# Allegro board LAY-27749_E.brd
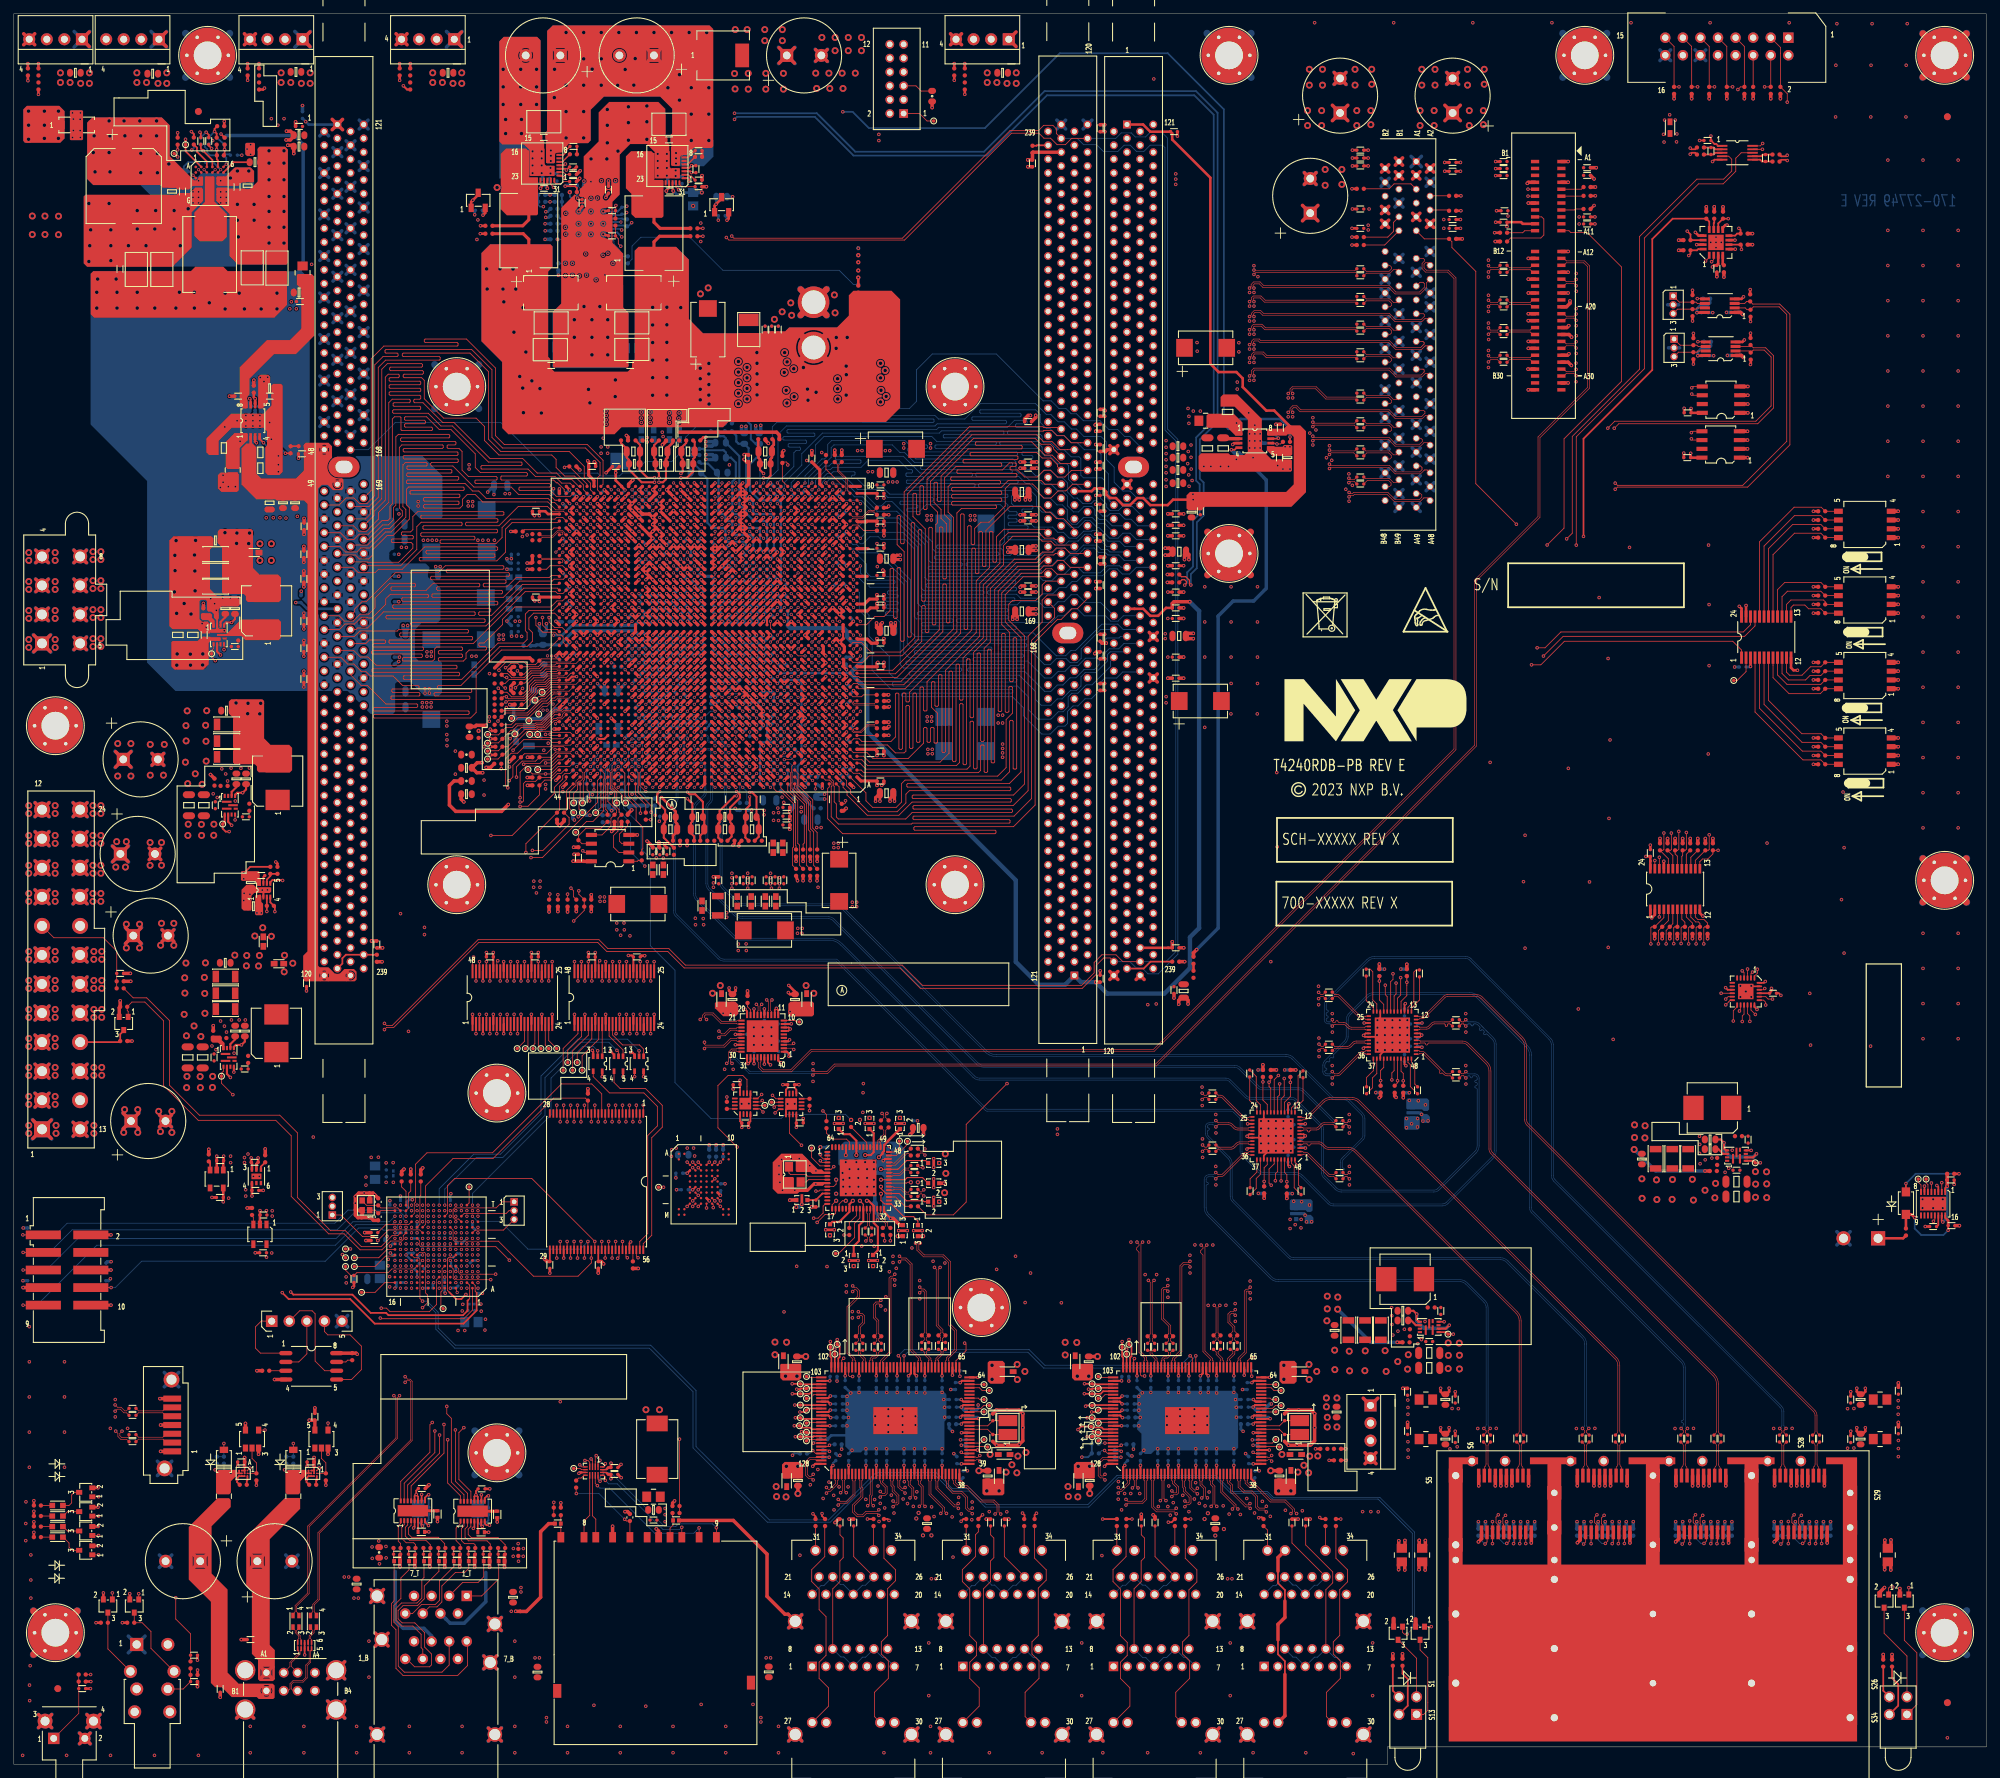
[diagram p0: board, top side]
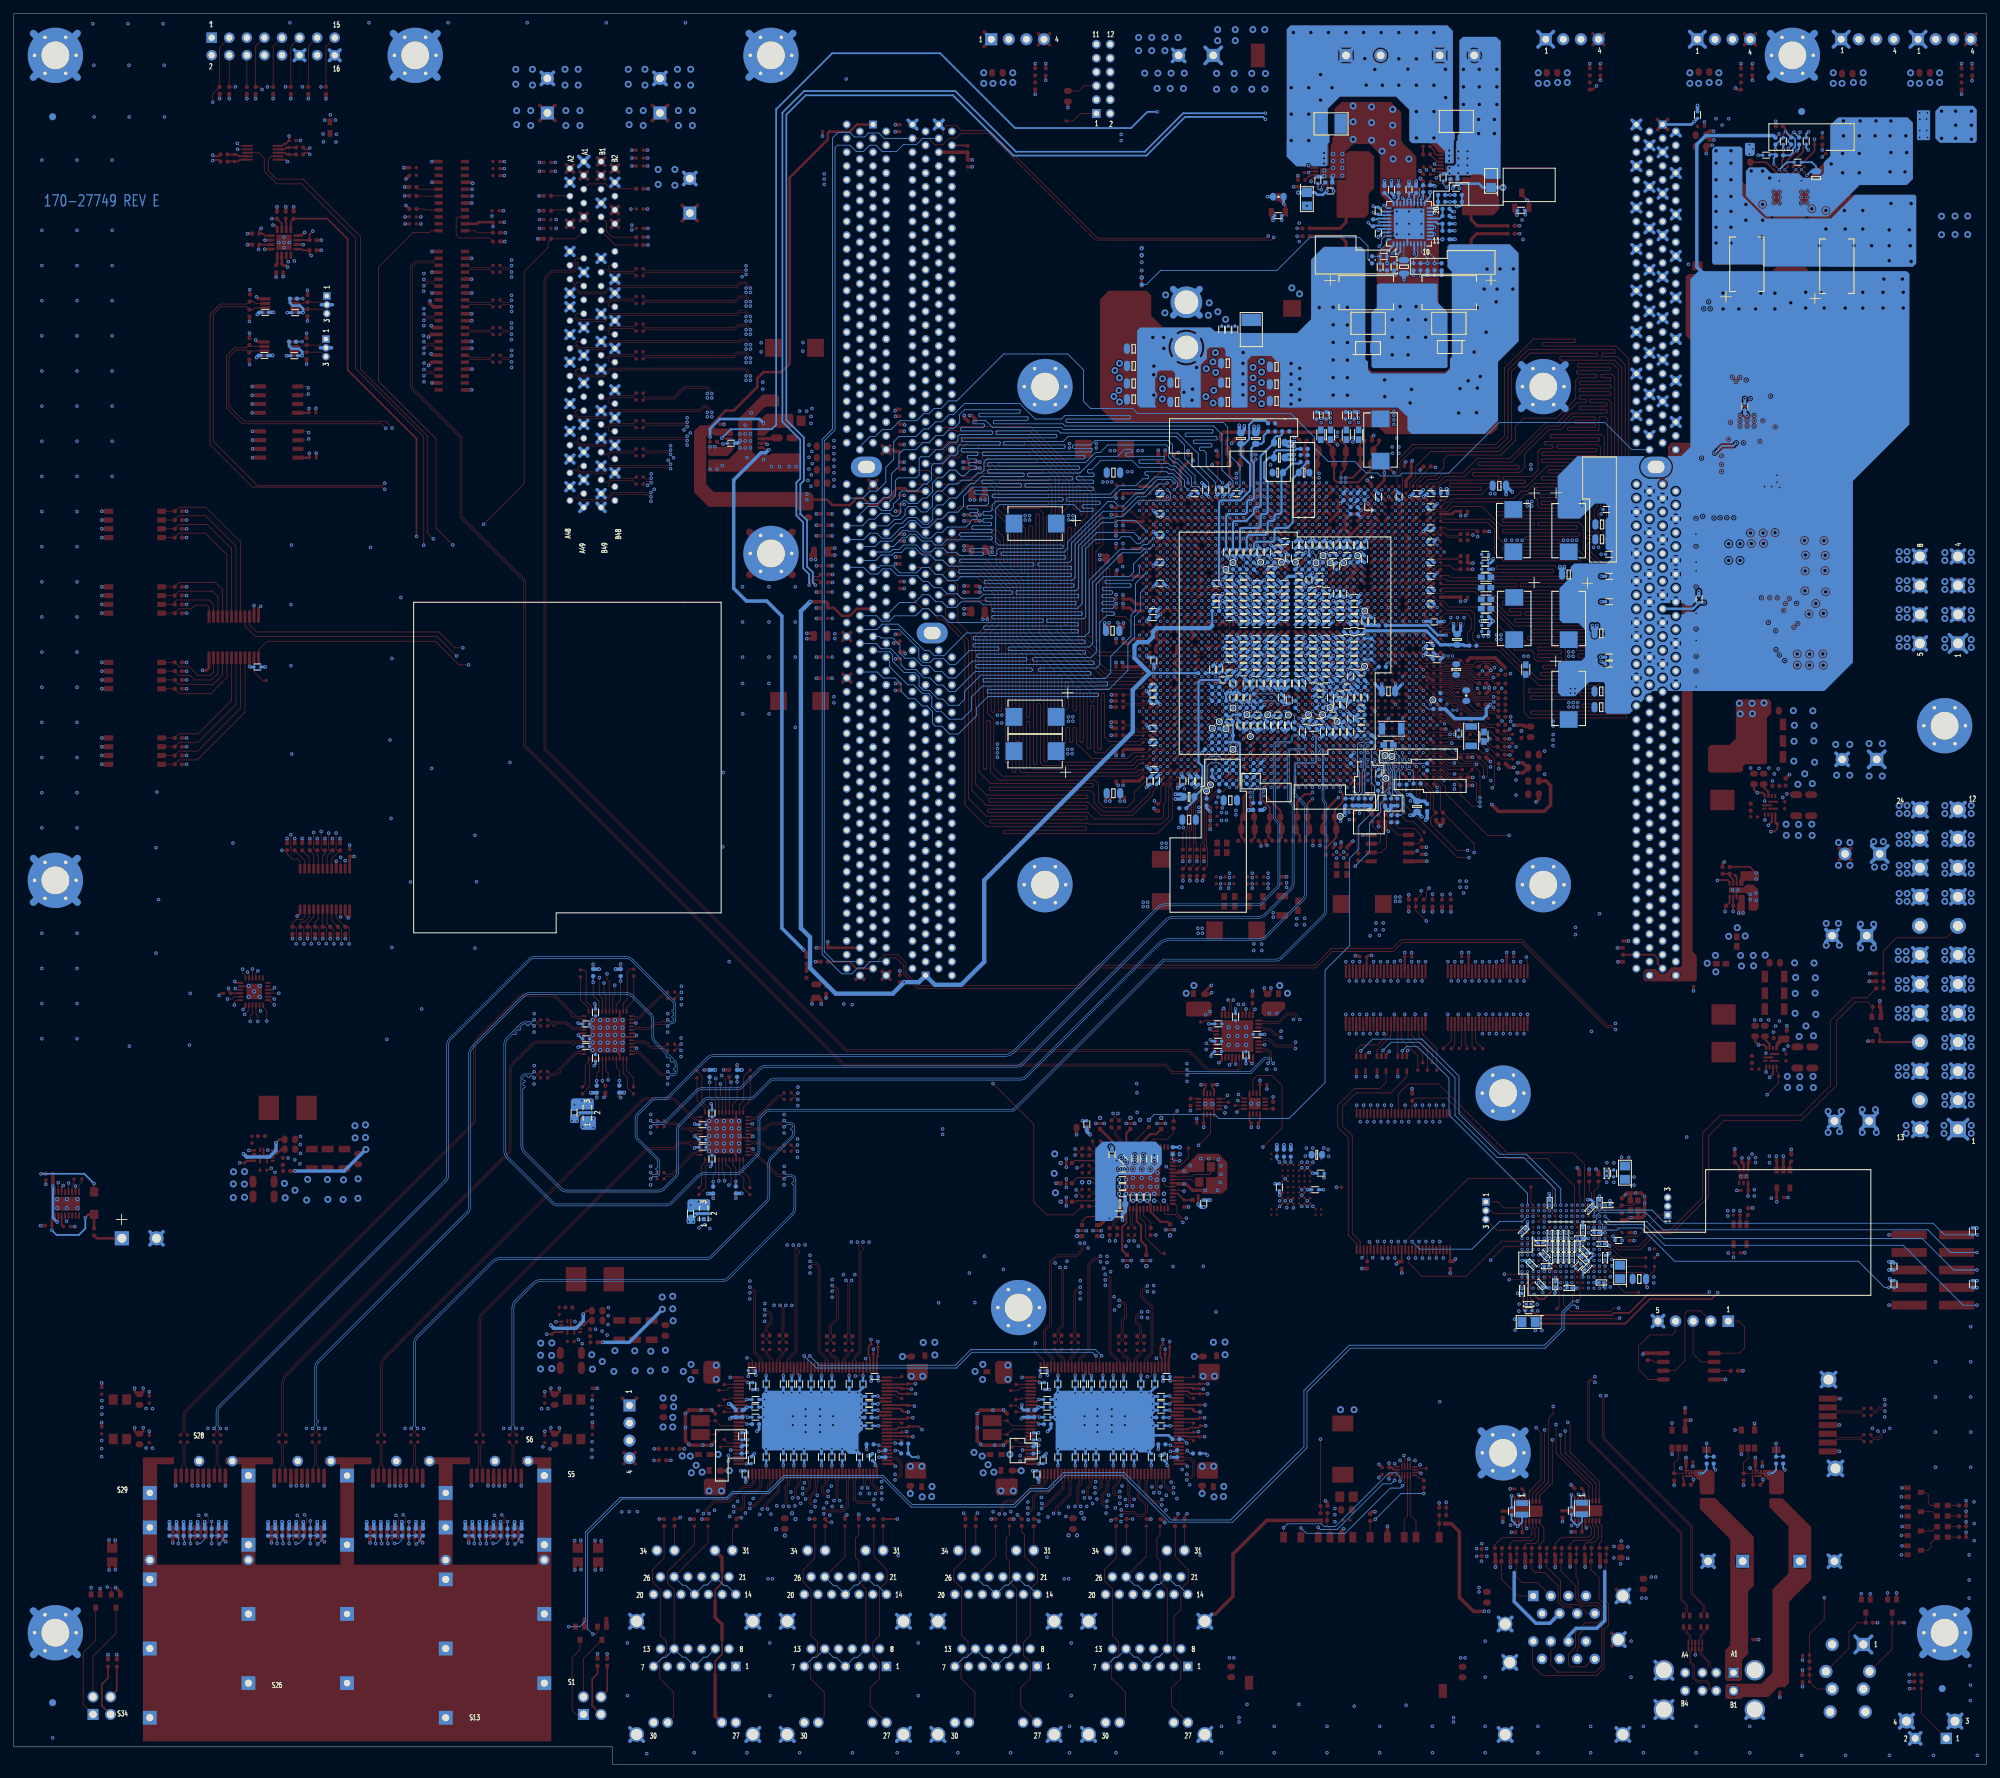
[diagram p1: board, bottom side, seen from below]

Outline 285 x 253 mm; copper layers: TOP, L2_GND_1, L3_INT_1, L4_GND_2, L5_INT_2, L6_GND_3, L7_INT_3, L8_PWR_1, L9_PWR_2, L10_INT_4, L11_GND_4, L12_INT_5, L13_GND_5, L14_INT_6, L15_GND_6, BOTTOM. Coordinates in mm from the lower left corner of the outline.
Outline path: 0,253 285,253 285,2.5 198.5,2.5 198.5,0 0,0 0,253

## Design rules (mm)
constraint set DEFAULT: min track width 0.118
net group ATXPWRGD: nets ATX_PWROK ATXPWRGD
net group CLK_PCIE_REF: nets CLK_PCIE_REF_N CLK_PCIE_REF_P
net group CLKU1: nets CLKU1_N CLKU1_P
net group CLKU2: nets CLKU2_N CLKU2_P
net group CLKU4: nets CLKU4_N CLKU4_P
net group CLKU5: nets CLKU5_N CLKU5_P
net group CLKU6: nets CLKU6_N CLKU6_P
net group CLKU7: nets CLKU7_N CLKU7_P
net group DP1: nets CLK_SE1_100MHZ CLK_SE2_100MHZ
net group DP2: nets EC1_GTX_CLK125 EC2_GTX_CLK125
net group I2C1_SCL: nets I2C1_SCL VDD_SCL
net group I2C1_SDA: nets I2C1_SDA VDD_SDA
net group INJ_DDRCLK: nets DDRCLK INJ_DDRCLK
net group ISOSDHC_CLK: nets ISOSDHC_CLK SDCK
net group LRST_BUTTON_B: nets LRST_BUTTON_B SW_RST_B
net group M1_VREF_ISO: nets M1_VREF_ISO M2_VREF_ISO
net group MC_PCIE_CLK_: nets PCIE_X4_CLK_N PCIE_X4_CLK_P
net group PCIE_REFCLK_: nets PCIE_REFCLK_N PCIE_REFCLK_P
net group RX1_L0_N: nets RX1_L0_N RX1_L0_N_DC
net group RX1_L0_P: nets RX1_L0_P RX1_L0_P_DC
net group RX2_L0_N: nets RX2_L0_N RX2_L0_N_DC
net group RX2_L0_P: nets RX2_L0_P RX2_L0_P_DC
net group RX3_L0_N: nets RX3_L0_N RX3_L0_N_DC
net group RX3_L0_P: nets RX3_L0_P RX3_L0_P_DC
net group RX4_L0_N: nets RX4_L0_N RX4_L0_N_DC
net group RX4_L0_P: nets RX4_L0_P RX4_L0_P_DC
net group SD1_REFCLK1_LVDS_: nets SD1_REFCLK1_N SD1_REFCLK1_P
net group SD2_REFCLK1_LVDS_: nets SD2_REFCLK1_N SD2_REFCLK1_P
net group SD2_REFCLK2_: nets SD2_REFCLK2_N SD2_REFCLK2_P
net group SD2_RX0_N: nets SD2_RX0_N XRX1_DOUTN
net group SD2_RX0_P: nets SD2_RX0_P XRX1_DOUTP
net group SD2_RX1_N: nets SD2_RX1_N XRX2_DOUTN
net group SD2_RX1_P: nets SD2_RX1_P XRX2_DOUTP
net group SD2_RX2_N: nets SD2_RX2_N XRX3_DOUTN
net group SD2_RX2_P: nets SD2_RX2_P XRX3_DOUTP
net group SD2_RX3_N: nets SD2_RX3_N XRX4_DOUTN
net group SD2_RX3_P: nets SD2_RX3_P XRX4_DOUTP
net group SD3_REFCLK1_: nets SD3_REFCLK1_N SD3_REFCLK1_P
net group SD4_REFCLK1_: nets SD4_REFCLK1_N SD4_REFCLK1_P
net group SD4_REFCLK2_: nets SD4_REFCLK2_N SD4_REFCLK2_P
net group SD4_RXC6_N: nets SD4_RX6_P SD4_RXC6_N
net group SD4_RXC6_P: nets SD4_RX6_N SD4_RXC6_P
net group SD4_TX1_N: nets SD4_TX1_N SD4_TXC1_N
net group SD4_TX1_P: nets SD4_TX1_P SD4_TXC1_P
net group SD4_TX2_N: nets SD4_TX2_N SD4_TXC2_N
net group SD4_TX2_P: nets SD4_TX2_P SD4_TXC2_P
net group SD4_TX3_N: nets SD4_TX3_N SD4_TXC3_N
net group SD4_TX3_P: nets SD4_TX3_P SD4_TXC3_P
net group SDHC_CD_B: nets SD_CD# SDHC_CD_B
net group SDHC_CLK: nets SDHC_CLK UT_SDHCCLK
net group SDHC_WP: nets SD_WP SDHC_WP
net group SPI_CE_B: nets SPI_CE_B SPI_CS0_B
net group SPI_CLK: nets SPI_CLK UT_SPICLK
net group SW_PWR_B: nets SW_PWR_B SW_PWR_OUT
net group TEMP_DIODE1_: nets TEMP_DIODE1_N TEMP_DIODE1_P
net group TEMP_DIODE2_: nets TEMP_DIODE2_N TEMP_DIODE2_P
net group TX1_L0_N: nets TX1_L0_N TX1_L0_N_DC
net group TX1_L0_P: nets TX1_L0_P TX1_L0_P_DC
net group TX2_L0_N: nets TX2_L0_N TX2_L0_N_DC
net group TX2_L0_P: nets TX2_L0_P TX2_L0_P_DC
net group TX3_L0_N: nets TX3_L0_N TX3_L0_N_DC
net group TX3_L0_P: nets TX3_L0_P TX3_L0_P_DC
net group TX4_L0_N: nets TX4_L0_N TX4_L0_N_DC
net group TX4_L0_P: nets TX4_L0_P TX4_L0_P_DC
net group VDD_SENSE0+: nets VDD_SENSE0+ VDD_SENSE_P
net group 5V0_SB: nets PS_ON_B
net group CLK_OTHER: nets CLK_ENET1 CLK_ENET2 RTCCLK_DUT
net group COP: nets COP_TCK COP_TDI COP_TDO COP_TMS COP_TRST_B
net group DATA_CLK: nets I2C1_CH0_SCL I2C1_CH0_SDA I2C1_CH3_SCL I2C1_CH3_SDA I2C1_PROC_SCL I2C1_PROC_SDA I2C2_PROC_SCL I2C2_PROC_SDA I2C2_SCL I2C2_SDA I2C4_SCL I2C4_SDA
net group DUT: nets DUT_DMA0 DUT_DMA1 DUT_DMA2 DUT_DMA3 DUT_DMA4 DUT_DMA5
net group DW4;4=6: nets M1_MCLK2_N M1_MCLK2_P M1_MCLK3_N M1_MCLK3_P M2_MCLK2_N M2_MCLK2_P M2_MCLK3_N M2_MCLK3_P M3_MCLK2_N M3_MCLK2_P M3_MCLK3_N M3_MCLK3_P
net group INJ_SYSCLK: nets SYSCLK
net group IRQ: nets IRQ_OUT_B
net group M3_VREF_ISO: nets M3_VREF_ISO
net group M_1G_P0: nets 1G_P0_TXVA_N 1G_P0_TXVA_P 1G_P0_TXVB_N 1G_P0_TXVB_P 1G_P0_TXVC_N 1G_P0_TXVC_P 1G_P0_TXVD_N 1G_P0_TXVD_P
net group M_1G_P1: nets 1G_P1_TXVA_N 1G_P1_TXVA_P 1G_P1_TXVB_N 1G_P1_TXVB_P 1G_P1_TXVC_N 1G_P1_TXVC_P 1G_P1_TXVD_N 1G_P1_TXVD_P
net group M_1G_P2: nets 1G_P2_TXVA_N 1G_P2_TXVA_P 1G_P2_TXVB_N 1G_P2_TXVB_P 1G_P2_TXVC_N 1G_P2_TXVC_P 1G_P2_TXVD_N 1G_P2_TXVD_P
net group M_1G_P3: nets 1G_P3_TXVA_N 1G_P3_TXVA_P 1G_P3_TXVB_N 1G_P3_TXVB_P 1G_P3_TXVC_N 1G_P3_TXVC_P 1G_P3_TXVD_N 1G_P3_TXVD_P
net group M_1G_P4: nets 1G_P4_TXVA_N 1G_P4_TXVA_P 1G_P4_TXVB_N 1G_P4_TXVB_P 1G_P4_TXVC_N 1G_P4_TXVC_P 1G_P4_TXVD_N 1G_P4_TXVD_P
net group M_1G_P5: nets 1G_P5_TXVA_N 1G_P5_TXVA_P 1G_P5_TXVB_N 1G_P5_TXVB_P 1G_P5_TXVC_N 1G_P5_TXVC_P 1G_P5_TXVD_N 1G_P5_TXVD_P
net group M_1G_P6: nets 1G_P6_TXVA_N 1G_P6_TXVA_P 1G_P6_TXVB_N 1G_P6_TXVB_P 1G_P6_TXVC_N 1G_P6_TXVC_P 1G_P6_TXVD_N 1G_P6_TXVD_P
net group M_1G_P7: nets 1G_P7_TXVA_N 1G_P7_TXVA_P 1G_P7_TXVB_N 1G_P7_TXVB_P 1G_P7_TXVC_N 1G_P7_TXVC_P 1G_P7_TXVD_N 1G_P7_TXVD_P
net group M_M1_CMD_CTL_CLK: nets M1_MA0 M1_MA1 M1_MA2 M1_MA3 M1_MA4 M1_MA5 M1_MA6 M1_MA7 M1_MA8 M1_MA9 M1_MA10 M1_MA11 M1_MA12 M1_MA13 M1_MA14 M1_MA15 M1_MBA0 M1_MBA1 M1_MBA2 M1_MCAS_B M1_MCKE0 M1_MCKE1 M1_MCLK0_N M1_MCLK0_P M1_MCLK1_N M1_MCLK1_P M1_MCS_B0 M1_MCS_B1 M1_MCS_B2 M1_MCS_B3 M1_MODT0 M1_MODT1 M1_MRAS_B M1_MWE_B M1_PAROUT
net group M_M1_D0: nets M1_MDQ0 M1_MDQ1 M1_MDQ2 M1_MDQ3 M1_MDQ4 M1_MDQ5 M1_MDQ6 M1_MDQ7 M1_MDQS_N0 M1_MDQS_N9 M1_MDQS_P0 M1_MDQS_P9
net group M_M1_D1: nets M1_MDQ8 M1_MDQ9 M1_MDQ10 M1_MDQ11 M1_MDQ12 M1_MDQ13 M1_MDQ14 M1_MDQ15 M1_MDQS_N1 M1_MDQS_N10 M1_MDQS_P1 M1_MDQS_P10
net group M_M1_D2: nets M1_MDQ16 M1_MDQ17 M1_MDQ18 M1_MDQ19 M1_MDQ20 M1_MDQ21 M1_MDQ22 M1_MDQ23 M1_MDQS_N2 M1_MDQS_N11 M1_MDQS_P2 M1_MDQS_P11
net group M_M1_D3: nets M1_MDQ24 M1_MDQ25 M1_MDQ26 M1_MDQ27 M1_MDQ28 M1_MDQ29 M1_MDQ30 M1_MDQ31 M1_MDQS_N3 M1_MDQS_N12 M1_MDQS_P3 M1_MDQS_P12
net group M_M1_D4: nets M1_MDQ32 M1_MDQ33 M1_MDQ34 M1_MDQ35 M1_MDQ36 M1_MDQ37 M1_MDQ38 M1_MDQ39 M1_MDQS_N4 M1_MDQS_N13 M1_MDQS_P4 M1_MDQS_P13
net group M_M1_D5: nets M1_MDQ40 M1_MDQ41 M1_MDQ42 M1_MDQ43 M1_MDQ44 M1_MDQ45 M1_MDQ46 M1_MDQ47 M1_MDQS_N5 M1_MDQS_N14 M1_MDQS_P5 M1_MDQS_P14
net group M_M1_D6: nets M1_MDQ48 M1_MDQ49 M1_MDQ50 M1_MDQ51 M1_MDQ52 M1_MDQ53 M1_MDQ54 M1_MDQ55 M1_MDQS_N6 M1_MDQS_N15 M1_MDQS_P6 M1_MDQS_P15
net group M_M1_D7: nets M1_MDQ56 M1_MDQ57 M1_MDQ58 M1_MDQ59 M1_MDQ60 M1_MDQ61 M1_MDQ62 M1_MDQ63 M1_MDQS_N7 M1_MDQS_N16 M1_MDQS_P7 M1_MDQS_P16
net group M_M1_D8: nets M1_MDQS_N8 M1_MDQS_N17 M1_MDQS_P8 M1_MDQS_P17 M1_MECC0 M1_MECC1 M1_MECC2 M1_MECC3 M1_MECC4 M1_MECC5 M1_MECC6 M1_MECC7
net group M_M2_CMD_CTL_CLK: nets M2_MA0 M2_MA1 M2_MA2 M2_MA3 M2_MA4 M2_MA5 M2_MA6 M2_MA7 M2_MA8 M2_MA9 M2_MA10 M2_MA11 M2_MA12 M2_MA13 M2_MA14 M2_MA15 M2_MBA0 M2_MBA1 M2_MBA2 M2_MCAS_B M2_MCKE0 M2_MCKE1 M2_MCLK0_N M2_MCLK0_P M2_MCLK1_N M2_MCLK1_P M2_MCS_B0 M2_MCS_B1 M2_MCS_B2 M2_MCS_B3 M2_MODT0 M2_MODT1 M2_MRAS_B M2_MWE_B M2_PAROUT
net group M_M2_D0: nets M2_MDQ0 M2_MDQ1 M2_MDQ2 M2_MDQ3 M2_MDQ4 M2_MDQ5 M2_MDQ6 M2_MDQ7 M2_MDQS_N0 M2_MDQS_N9 M2_MDQS_P0 M2_MDQS_P9
net group M_M2_D1: nets M2_MDQ8 M2_MDQ9 M2_MDQ10 M2_MDQ11 M2_MDQ12 M2_MDQ13 M2_MDQ14 M2_MDQ15 M2_MDQS_N1 M2_MDQS_N10 M2_MDQS_P1 M2_MDQS_P10
net group M_M2_D2: nets M2_MDQ16 M2_MDQ17 M2_MDQ18 M2_MDQ19 M2_MDQ20 M2_MDQ21 M2_MDQ22 M2_MDQ23 M2_MDQS_N2 M2_MDQS_N11 M2_MDQS_P2 M2_MDQS_P11
net group M_M2_D3: nets M2_MDQ24 M2_MDQ25 M2_MDQ26 M2_MDQ27 M2_MDQ28 M2_MDQ29 M2_MDQ30 M2_MDQ31 M2_MDQS_N3 M2_MDQS_N12 M2_MDQS_P3 M2_MDQS_P12
net group M_M2_D4: nets M2_MDQ32 M2_MDQ33 M2_MDQ34 M2_MDQ35 M2_MDQ36 M2_MDQ37 M2_MDQ38 M2_MDQ39 M2_MDQS_N4 M2_MDQS_N13 M2_MDQS_P4 M2_MDQS_P13
net group M_M2_D5: nets M2_MDQ40 M2_MDQ41 M2_MDQ42 M2_MDQ43 M2_MDQ44 M2_MDQ45 M2_MDQ46 M2_MDQ47 M2_MDQS_N5 M2_MDQS_N14 M2_MDQS_P5 M2_MDQS_P14
net group M_M2_D6: nets M2_MDQ48 M2_MDQ49 M2_MDQ50 M2_MDQ51 M2_MDQ52 M2_MDQ53 M2_MDQ54 M2_MDQ55 M2_MDQS_N6 M2_MDQS_N15 M2_MDQS_P6 M2_MDQS_P15
net group M_M2_D7: nets M2_MDQ56 M2_MDQ57 M2_MDQ58 M2_MDQ59 M2_MDQ60 M2_MDQ61 M2_MDQ62 M2_MDQ63 M2_MDQS_N7 M2_MDQS_N16 M2_MDQS_P7 M2_MDQS_P16
net group M_M2_D8: nets M2_MDQS_N8 M2_MDQS_N17 M2_MDQS_P8 M2_MDQS_P17 M2_MECC0 M2_MECC1 M2_MECC2 M2_MECC3 M2_MECC4 M2_MECC5 M2_MECC6 M2_MECC7
net group M_M3_CMD_CTL_CLK: nets M3_MA0 M3_MA1 M3_MA2 M3_MA3 M3_MA4 M3_MA5 M3_MA6 M3_MA7 M3_MA8 M3_MA9 M3_MA10 M3_MA11 M3_MA12 M3_MA13 M3_MA14 M3_MA15 M3_MBA0 M3_MBA1 M3_MBA2 M3_MCAS_B M3_MCKE0 M3_MCKE1 M3_MCLK0_N M3_MCLK0_P M3_MCLK1_N M3_MCLK1_P M3_MCS_B0 M3_MCS_B1 M3_MCS_B2 M3_MCS_B3 M3_MODT0 M3_MODT1 M3_MRAS_B M3_MWE_B M3_PAROUT
net group M_M3_D0: nets M3_MDQ0 M3_MDQ1 M3_MDQ2 M3_MDQ3 M3_MDQ4 M3_MDQ5 M3_MDQ6 M3_MDQ7 M3_MDQS_N0 M3_MDQS_N9 M3_MDQS_P0 M3_MDQS_P9
net group M_M3_D1: nets M3_MDQ8 M3_MDQ9 M3_MDQ10 M3_MDQ11 M3_MDQ12 M3_MDQ13 M3_MDQ14 M3_MDQ15 M3_MDQS_N1 M3_MDQS_N10 M3_MDQS_P1 M3_MDQS_P10
net group M_M3_D2: nets M3_MDQ16 M3_MDQ17 M3_MDQ18 M3_MDQ19 M3_MDQ20 M3_MDQ21 M3_MDQ22 M3_MDQ23 M3_MDQS_N2 M3_MDQS_N11 M3_MDQS_P2 M3_MDQS_P11
net group M_M3_D3: nets M3_MDQ24 M3_MDQ25 M3_MDQ26 M3_MDQ27 M3_MDQ28 M3_MDQ29 M3_MDQ30 M3_MDQ31 M3_MDQS_N3 M3_MDQS_N12 M3_MDQS_P3 M3_MDQS_P12
net group M_M3_D4: nets M3_MDQ32 M3_MDQ33 M3_MDQ34 M3_MDQ35 M3_MDQ36 M3_MDQ37 M3_MDQ38 M3_MDQ39 M3_MDQS_N4 M3_MDQS_N13 M3_MDQS_P4 M3_MDQS_P13
net group M_M3_D5: nets M3_MDQ40 M3_MDQ41 M3_MDQ42 M3_MDQ43 M3_MDQ44 M3_MDQ45 M3_MDQ46 M3_MDQ47 M3_MDQS_N5 M3_MDQS_N14 M3_MDQS_P5 M3_MDQS_P14
net group M_M3_D6: nets M3_MDQ48 M3_MDQ49 M3_MDQ50 M3_MDQ51 M3_MDQ52 M3_MDQ53 M3_MDQ54 M3_MDQ55 M3_MDQS_N6 M3_MDQS_N15 M3_MDQS_P6 M3_MDQS_P15
net group M_M3_D7: nets M3_MDQ56 M3_MDQ57 M3_MDQ58 M3_MDQ59 M3_MDQ60 M3_MDQ61 M3_MDQ62 M3_MDQ63 M3_MDQS_N7 M3_MDQS_N16 M3_MDQS_P7 M3_MDQS_P16
net group M_M3_D8: nets M3_MDQS_N8 M3_MDQS_N17 M3_MDQS_P8 M3_MDQS_P17 M3_MECC0 M3_MECC1 M3_MECC2 M3_MECC3 M3_MECC4 M3_MECC5 M3_MECC6 M3_MECC7
net group NAND_NOR: nets IFC_AD0 IFC_AD1 IFC_AD2 IFC_AD3 IFC_AD4 IFC_AD5 IFC_AD6 IFC_AD7 IFC_AD8 IFC_AD9 IFC_AD10 IFC_AD11 IFC_AD12 IFC_AD13 IFC_AD14 IFC_AD15 IFC_AD16 IFC_AD17 IFC_AD18 IFC_AD19 IFC_AD20 IFC_AD21 IFC_AD22 IFC_AD23 IFC_AD24 IFC_AD25 IFC_AD26 IFC_AD27 IFC_AD28 IFC_AD29 IFC_AD30 IFC_AD31 IFC_AVD IFC_CS0_B IFC_CS1_B IFC_CS2_B IFC_CS3_B IFC_NOR_WE_B IFC_RB0_B IFC_RB1_B IFC_WE0_B IFC_WE2_B RST_IFC_B
net group OTHER: nets ASLEEP CFG_TESTSEL_B DUT_HRESET_B DUT_PORESET_B ORIENT_ERR_B
net group PWR_TRACE: nets 1V8_SB 1V8SB_EN 3V3_SB 3V3SB_EN 12V0_2_VDD_FLT 12V0_FILTERED_PS_GVDD AGND_SRDS1_PLL1 AGND_SRDS1_PLL2 AGND_SRDS2_PLL1 AGND_SRDS2_PLL2 AGND_SRDS3_PLL1 AGND_SRDS3_PLL2 AGND_SRDS4_PLL1 AGND_SRDS4_PLL2 AVDD_CGA2 AVDD_CGA3 AVDD_CGB1 AVDD_CGB2 AVDD_PLAT AVDD_SRDS1_PLL1 AVDD_SRDS1_PLL2 AVDD_SRDS2_PLL1 AVDD_SRDS2_PLL2 AVDD_SRDS3_PLL1 AVDD_SRDS3_PLL2 AVDD_SRDS4_PLL1 AVDD_SRDS4_PLL2 DIMM1_SA1 DIMM2_SA2 DIMM3_SA FA_ANALOG_PIN FAN1_PWM FAN1_TACH FAN2_PWM FAN2_TACH FAN3_PWM FAN3_TACH FAN4_PWM FAN5_PWM FAN_ADDR FAN_DEF GVDD GVDD_FB GVDD_FDIVH GVDD_FDIVL GVDD_GND GVDD_INTVCC GVDD_ITH GVDD_ITHX GVDD_MS GVDD_RT GVDD_SENSE GVDD_SVIN GVDD_TRK GVDD_VOUTM GVSS_SENSE IRQ_FAN_B LV_TACH1 LV_TACH2 LV_TACH3 LV_TACH4 LV_TACH5 M_VTT_A M_VTT_B N16616368 N18839314 N18839320 N18839524 N18839526 N18839532 N31148954 N31148956 N31149103 N31149105 N31714319 N31714572 N31717308 N31718323 N31724252 N31726596 N31727679 N31789752 N31789971 N31790039 N31884769 N31885020 N31888256 N31888301 N32105138 N32110539 N32112200 N32114233 N32114429 N32114439 N32122553 N32122566 N32123048 N32123323 N33496283 N33521274 N34325441 N311488790 N311490280 P1_LINKACT_P P2_LINKACT_P P3_LINKACT_P P4_LINKACT_P PEXBUFCOREV PEXBUFIOV PHY0_AVDD18 PHY0_AVDD33 PHY0_CLKSEL0 PHY0_CLKSEL1 PHY0_VDDORL PHY1_AVDD18 PHY1_AVDD33 PHY1_CLKSEL0 PHY1_CLKSEL1 PHY1_VDDORL PHY_1V0 POVDD PROG_MTR PROG_SFP PS_2V5_EN PS_2V5_PG PS_GVDD_EN PS_GVDD_PG PS_OVDD_PG PS_PHY_1V8_EN PS_PHY_1V8_PG PS_POVDD_EN PS_POVDD_PG PS_VDD_EN PS_VDD_PG PS_VTT_EN PS_XVDD_EN RT1_2V5 RT2_2V5 RTCVSB SVDD UART1_SW UART2_SW USB1_ILIM USB1_ISOPWR USB2_ILIM USB2_ISOPWR USB_HVDD USB_OVDD USB_SVDD VBUS_POWER1 VBUS_POWER2 VDD VDD_ASEL0 VDD_ASEL1 VDD_COMP0 VDD_COMP1 VDD_FA_VDD VDD_FB1 VDD_FREQ_CFG VDD_ISENSE0+ VDD_ISENSE0- VDD_ISENSE1+ VDD_ISENSE1- VDD_LP VDD_OVDD_P1V8 VDD_PH1_FLT VDD_PH2_FLT VDD_PHAS_CFG VDD_PWM0 VDD_PWM1 VDD_SENSE0- VDD_SENSE_N VDD_SH_CLK VDD_TH_VDD VDD_TSNS0 VDD_TSNS1 VDD_VOUT_CFG VDD_VSENSE1+ VTT_A_SENSE VTT_B_SENSE XVDD Z5402
net group S5/20: nets DUT_RESET_REQ_B IFC_A26 IFC_A27 IFC_A28 IFC_A29 IFC_A30 IFC_A31 IFC_CLE IFC_NAND_CS_B IFC_NOR_CS_B
net group S25: nets CLK_USB CLK_USB_DUT INJ_SYSCLK SD3_REFCLK2_N SD3_REFCLK2_P SD4_TX6_N SD4_TX6_P SD4_TXC6_N SD4_TXC6_P TEMP_ANODE1_ADT TEMP_ANODE2_ADT TEMP_CATHODE1_ADT TEMP_CATHODE2_ADT
net group S35: nets R_SD1_RX4_N R_SD1_RX4_P R_SD1_RX5_N R_SD1_RX5_P R_SD1_RX6_N R_SD1_RX6_P R_SD1_RX7_N R_SD1_RX7_P R_SD2_RX4_N R_SD2_RX4_P R_SD2_RX5_N R_SD2_RX5_P R_SD2_RX6_N R_SD2_RX6_P R_SD2_RX7_N R_SD2_RX7_P R_SD2_TX0_N R_SD2_TX0_P R_SD2_TX1_N R_SD2_TX1_P R_SD2_TX2_N R_SD2_TX2_P R_SD2_TX3_N R_SD2_TX3_P SD1_RX4_N SD1_RX4_P SD1_RX5_N SD1_RX5_P SD1_RX6_N SD1_RX6_P SD1_RX7_N SD1_RX7_P SD1_TX4_N SD1_TX4_P SD1_TX5_N SD1_TX5_P SD1_TX6_N SD1_TX6_P SD1_TX7_N SD1_TX7_P SD2_RX4_N SD2_RX4_P SD2_RX5_N SD2_RX5_P SD2_RX6_N SD2_RX6_P SD2_RX7_N SD2_RX7_P SD2_TX0_N SD2_TX0_P SD2_TX1_N SD2_TX1_P SD2_TX2_N SD2_TX2_P SD2_TX3_N SD2_TX3_P SD2_TX4_N SD2_TX4_P SD2_TX5_N SD2_TX5_P SD2_TX6_N SD2_TX6_P SD2_TX7_N SD2_TX7_P SD3_RX1_N SD3_RX1_P SD3_RX4_N SD3_RX4_P SD3_RX5_N SD3_RX5_P SD3_TX0_N SD3_TX0_P SD3_TX1_N SD3_TX1_P SD3_TX2_N SD3_TX2_P SD3_TX3_N SD3_TX3_P SD3_TX4_N SD3_TX4_P SD3_TX5_N SD3_TX5_P SD3_TX6_N SD3_TX6_P SD3_TX7_N SD3_TX7_P SD3_TXC0_N SD3_TXC0_P SD3_TXC1_N SD3_TXC1_P SD3_TXC2_N SD3_TXC2_P SD3_TXC3_N SD3_TXC3_P SD3_TXC4_N SD3_TXC4_P SD3_TXC5_N SD3_TXC5_P SD3_TXC6_N SD3_TXC6_P SD3_TXC7_N SD3_TXC7_P SD4_RX1_N SD4_RX1_P SD4_TX0_N SD4_TX0_P SD4_TXC0_N SD4_TXC0_P USB1_DN USB1_DP USB1_ISON USB1_ISOP USB2_DN USB2_DP USB2_ISON USB2_ISOP
net group SD: nets SDHC_CMD SDHC_DAT0 SDHC_DAT1 SDHC_DAT2 SDHC_DAT3
net group SD4: nets SD4_RX0_N SD4_RX0_P SD4_RX2_N SD4_RX2_P SD4_RX3_N SD4_RX3_P
net group UPART: nets DUT_UART1_CTS_B DUT_UART1_RTS_B DUT_UART1_RXD DUT_UART1_TXD DUT_UART2_CTS_B DUT_UART2_RTS_B DUT_UART2_RXD DUT_UART2_TXD
net group USBID: nets USB1_PWREN USB1_PWRFLT_B USB2_PWREN USB2_PWRFLT_B USB2_VBUSCLMP
net group W10: nets 1G_P0_LED_ACT_N 1G_P0_LINK10_100_N 1G_P0_LINK1000_N 1G_P1_LED_ACT_N 1G_P1_LINK10_100_N 1G_P1_LINK1000_N 1G_P2_LED_ACT_N 1G_P2_LINK10_100_N 1G_P2_LINK1000_N 1G_P3_LED_ACT_N 1G_P3_LINK10_100_N 1G_P3_LINK1000_N 1G_P4_LED_ACT_N 1G_P4_LINK10_100_N 1G_P4_LINK1000_N 1G_P5_LED_ACT_N 1G_P5_LINK10_100_N 1G_P5_LINK1000_N 1G_P6_LED_ACT_N 1G_P6_LINK10_100_N 1G_P6_LINK1000_N 1G_P7_LED_ACT_N 1G_P7_LINK10_100_N 1G_P7_LINK1000_N AVDD_CGA1 AVDD_DDR1 AVDD_DDR2 AVDD_DDR3 CKGEN_VDDO0 CKGEN_VDDO1 CKGEN_VDDO2 CKGEN_VDDO3 CKGEN_VDDO4 CKGEN_VDDO5 CKGEN_VDDO6 CKGEN_VDDO7 CKGEN_VDDO8 CKGEN_VDDO9 N37212649 SI5341_VDD SI5341_VDDA VBBS

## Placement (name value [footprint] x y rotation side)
BH9  MH_180  [MH180-135P]  115.56 204.77 270 top
BH10  MH_180  [MH180-135P]  115.56 211.31 270 top
C1  1uF  [CC0603_OV]  33.38 105.97 270 top
C2  0.1uF  [CC0402_HD]  33.35 100.48 0 top
C3  10uF  [CC1206_OV]  25.12 102.16 90 top
C4  10uF  [CC1206_OV]  27.28 102.16 90 top
C5  0.1uF  [CC0402_HD]  28.93 102.16 270 top
C6  22uF  [1206_CC]  30.58 111.43 180 top
C7  0.1uF  [CC0402_HD]  244.73 234.7 180 top
C8  22uF  [1206_CC]  30.58 113.84 180 top
C9  1000pF  [CC0402_HD]  245.24 233.17 270 top
C10  0.047UF  [CC0603_OV]  31.98 105.97 90 top
C12  1000pF  [CC0402_HD]  253.11 232.16 270 top
C15  1uF  [CC0603_OV]  8.89 244.47 0 top
C16  1uF  [CC0603_OV]  40.77 244.6 0 top
C17  1uF  [CC0603_OV]  62.74 244.47 0 top
C18  1uF  [CC0603_OV]  142.88 244.47 0 top
C25  0.1uF  [CC0402_HD]  194.56 233.3 180 top
C26  0.1uF  [CC0402_HD]  207.9 230.25 0 top
C27  0.1uF  [CC0402_HD]  41.71 238.38 90 bottom
C28  0.1uF  [CC0402_HD]  156.97 236.47 270 top
C35  0.1uF  [CC0402_HD]  167.64 235.97 0 top
C40  0.1uF  [CC0402_HD]  194.56 231.01 180 top
C41  0.1uF  [CC0402_HD]  207.9 231.52 0 top
C42  0.1uF  [CC0402_HD]  147.19 231.39 270 top
C43  0.1uF  [CC0402_HD]  194.56 232.16 180 top
C58  0.1uF  [CC0402_HD]  194.56 224.79 180 top
C60  0.1uF  [CC0402_HD]  207.9 223.27 0 top
C65  0.1uF  [CC0402_HD]  194.56 222 180 top
C66  0.1uF  [CC0402_HD]  207.9 222 0 top
C76  0.1uF  [CC0402_HD]  194.56 216.15 0 top
C78  0.1uF  [CC0402_HD]  194.56 215.14 0 top
C79  0.1uF  [CC0402_HD]  194.56 212.15 0 top
C80  0.1uF  [CC0402_HD]  194.56 211.14 0 top
C81  0.1uF  [CC0402_HD]  194.56 208.15 0 top
C82  0.1uF  [CC0402_HD]  194.56 207.14 0 top
C83  1uF  [CC0603_OV]  41.21 212.72 180 top
C84  4.7uF  [CC0603_OV]  36.96 198.88 0 top
C85  1uF  [CC0402_HD]  76.6 227.79 180 bottom
C86  1uF  [CC0402_HD]  82.12 225.65 270 top
C87  0.1uF  [CC0402_HD]  80.86 233.84 0 top
C88  0.1uF  [CC0402_HD]  194.56 204.15 0 top
C89  0.1uF  [CC0402_HD]  32.41 197.74 0 top
C90  0.1uF  [CC0402_HD]  194.56 203.14 0 top
C91  100uF  [CC1210]  77.64 208.27 0 bottom
C92  2.2uF  [CC0402_HD]  85.93 227.58 270 bottom
C93  1uF  [CC0402_HD]  85.93 227.58 270 top
C94  0.1uF  [CC0402_HD]  85.55 216.43 270 bottom
C95  0.1uF  [CC0402_HD]  194.56 198.18 0 top
C96  0.1uF  [CC0402_HD]  194.56 197.17 0 top
C97  0.1uF  [CC0402_HD]  78.48 229.34 90 bottom
C98  22uF  [CC0805]  77.51 204.84 0 bottom
C99  0.22uF  [CC0402_HD]  87.83 221.26 270 bottom
C101  0.01UF  [CC0402_HD]  102.29 223.82 0 bottom
C102  0.1uF  [CC0402_HD]  156.97 195.33 270 top
C103  0.1uF  [CC0402_HD]  194.56 194.18 0 top
C104  0.1uF  [CC0402_HD]  146.56 194.06 0 top
C105  4.7uF  [CC0603_OV]  184.02 188.85 270 top
C106  0.1uF  [CC0402_HD]  156.97 193.17 270 top
C107  100uF  [CC1210]  106.19 207.36 90 top
C108  0.1uF  [CC0402_HD]  194.56 193.17 0 top
C109  0.01UF  [CC0402_HD]  110.46 207.36 90 bottom
C110  0.01UF  [CC0402_HD]  110.46 207.36 90 top
C112  0.1uF  [CC0402_HD]  248.79 203.62 180 bottom
C113  0.1uF  [CC0402_HD]  244.47 203.58 0 bottom
C114  2.2uF  [CC0402_HD]  108.56 207.36 90 bottom
C115  56PF  [CC0402_HD]  86.44 220.91 180 top
C116  56PF  [CC0402_HD]  86.44 224.55 180 top
C117  0.1uF  [CC0402_HD]  156.97 190.25 90 top
C118  0.1uF  [CC0402_HD]  194.56 190.12 0 top
C119  0.1uF  [CC0402_HD]  41.63 189.41 180 top
C120  47uF  [CC0805_OV]  89.52 189.74 180 top
C121  47uF  [CC0805_OV]  93.48 189.74 0 top
C122  47uF  [CC0805_OV]  97.42 189.74 0 top
C123  47uF  [CC0805_OV]  108.57 189.74 180 top
C124  0.1uF  [CC0402_HD]  98.94 233.22 0 top
C125  0.1uF  [CC0402_HD]  183.01 193.17 270 top
C126  0.1uF  [CC0402_HD]  194.56 189.1 0 top
C127  0.1uF  [CC0402_HD]  96.56 228.97 90 bottom
C128  0.1uF  [CC0402_HD]  106.17 188.72 90 top
C129  0.1uF  [CC0402_HD]  115.32 188.72 90 top
C130  0.1uF  [CC0402_HD]  146.56 188.21 0 top
C131  22uF  [CC0805]  89.32 204.67 180 bottom
C133  4.7uF  [CC0603_OV]  89.66 187.96 180 top
C134  4.7uF  [CC0603_OV]  93.47 187.96 0 top
C135  4.7uF  [CC0603_OV]  97.41 187.96 0 top
C136  4.7uF  [CC0603_OV]  108.58 187.96 180 top
C137  0.1uF  [CC0402_HD]  156.97 187.71 270 top
C138  0.1uF  [CC0402_HD]  83.57 187.58 0 top
C141  0.1uF  [CC0402_HD]  146.56 187.32 180 top
C143  47uF  [CC0805_OV]  126.11 186.69 0 top
C144  0.1uF  [CC0402_HD]  248.67 209.84 180 bottom
C145  0.1uF  [CC0402_HD]  227.33 230.76 0 top
C147  0.1uF  [CC0402_HD]  194.56 186.06 0 top
C148  47uF  [CC0805_OV]  169.04 111.76 270 top
C149  0.1uF  [CC0402_HD]  194.56 185.04 0 top
C150  0.1uF  [CC0402_HD]  125.22 184.91 0 top
C151  47uF  [CC0805_OV]  145.66 183.9 180 top
C152  0.1uF  [CC0402_HD]  156.97 183.9 270 top
C153  0.1uF  [CC0402_HD]  167.89 179.07 180 top
C157  0.1uF  [CC0402_HD]  125.22 183.7 0 top
C158  0.1uF  [CC0402_HD]  41.94 178.92 270 top
C159  0.1uF  [CC0402_HD]  156.97 181.61 270 top
C161  0.1uF  [CC0402_HD]  75.44 181.1 180 top
C162  0.1uF  [CC0402_HD]  167.89 180.72 180 top
C163  0.1uF  [CC0402_HD]  146.56 180.59 180 top
C164  0.1uF  [CC0402_HD]  146.56 179.71 180 top
C165  0.1uF  [CC0402_HD]  125.22 179.68 0 top
C166  0.1uF  [CC0402_HD]  167.89 177.55 180 top
C167  0.1uF  [CC0402_HD]  156.97 177.29 90 top
C168  0.1uF  [CC0402_HD]  125.22 175.77 0 top
C169  47uF  [CC0805_OV]  145.66 175.51 0 top
C170  47uF  [CC0805_OV]  168.41 175.26 0 top
C171  0.1uF  [CC0402_HD]  227.33 229.65 0 top
C172  0.1uF  [CC0402_HD]  41.91 174.88 90 top
C173  47uF  [CC0805_OV]  126.11 174.24 0 top
C176  0.1uF  [CC0402_HD]  156.97 173.99 90 top
C179  0.1uF  [CC0402_HD]  167.89 173.23 180 top
C182  0.1uF  [CC0402_HD]  125.22 171.83 0 top
C185  0.1uF  [CC0402_HD]  41.91 171.33 270 top
C186  0.1uF  [CC0402_HD]  156.97 170.43 270 top
C187  0.1uF  [CC0402_HD]  146.56 170.31 0 top
C189  0.1uF  [CC0402_HD]  146.56 169.42 0 top
C190  0.1uF  [CC0402_HD]  167.89 169.42 0 top
C191  0.1uF  [CC0402_HD]  75.44 168.7 180 top
C192  0.1uF  [CC0402_HD]  125.22 168.4 0 top
C196  0.1uF  [CC0402_HD]  125.22 167.13 0 top
C197  0.1uF  [CC0402_HD]  167.89 167.13 0 top
C199  47uF  [CC0805_OV]  145.66 166.62 180 top
C201  0.1uF  [CC0402_HD]  167.89 165.61 180 top
C202  0.1uF  [CC0402_HD]  41.91 165.23 270 top
C205  47uF  [CC0805_OV]  126.11 163.83 0 top
C207  47uF  [CC0805_OV]  168.39 163.07 180 top
C208  0.1uF  [CC0402_HD]  156.97 162.81 90 top
C209  0.1uF  [CC0402_HD]  125.22 162.05 0 top
C211  0.1uF  [CC0402_HD]  41.91 161.3 270 top
C215  0.1uF  [CC0402_HD]  156.97 160.27 270 top
C216  0.1uF  [CC0402_HD]  167.89 160.02 0 top
C218  0.1uF  [CC0402_HD]  125.22 158.62 0 top
C220  0.1uF  [CC0402_HD]  167.89 156.97 0 top
C221  0.1uF  [CC0402_HD]  41.91 156.85 270 top
C224  0.22uF  [CC0402_HD]  208.38 107.6 180 top
C225  0.22uF  [CC0402_HD]  208.38 106.69 180 top
C226  0.22uF  [CC0402_HD]  208.39 100.1 180 top
C227  0.22uF  [CC0402_HD]  208.39 99.18 180 top
C228  0.22uF  [CC0402_HD]  191.55 93.03 180 top
C229  0.22uF  [CC0402_HD]  191.55 92.11 180 top
C230  0.22uF  [CC0402_HD]  191.56 85.52 180 top
C231  0.22uF  [CC0402_HD]  191.56 84.61 180 top
C240  0.1uF  [CC0402_HD]  156.97 155.7 270 top
C246  0.1uF  [CC0402_HD]  125.22 146.43 0 top
C250  10uF  [CC0603_OV]  65.41 144.02 0 top
C251  0.1uF  [CC0402_HD]  125.22 142.11 0 top
C252  10uF  [CC0603_OV]  65.41 140.21 180 top
C253  47uF  [CC0805_OV]  126.11 140.34 0 top
C254  0.01UF  [CC0402_HD]  35.76 128.45 0 top
C255  10uF  [CC0603_OV]  34.24 127.43 270 top
C256  10uF  [CC0603_OV]  34.62 124 180 top
C258  3300pF  [CC0402_HD]  111.63 138.3 0 top
C259  2.2uF  [CC0402_HD]  111.63 137.03 0 top
C260  4.7uF  [CC0603_OV]  94.87 136.91 0 top
C261  4.7uF  [CC0603_OV]  98.81 136.91 180 top
C262  4.7uF  [CC0603_OV]  102.74 136.91 0 top
C263  4.7uF  [CC0603_OV]  106.55 136.91 180 top
C265  2.2uF  [CC0402_HD]  111.63 135.76 0 top
C268  47uF  [CC0805_OV]  94.88 135.13 0 top
C269  47uF  [CC0805_OV]  98.79 135.13 180 top
C270  47uF  [CC0805_OV]  102.76 135.13 0 top
C271  47uF  [CC0805_OV]  106.67 135.13 180 top
C273  2.2uF  [CC0402_HD]  92.33 131.95 90 top
C274  3300pF  [CC0402_HD]  93.34 131.95 90 top
C275  2.2uF  [CC0402_HD]  94.36 131.95 90 top
C276  0.1uF  [CC0402_HD]  81.58 131.01 90 top
C280  2.2uF  [CC0402_HD]  101.85 127.76 90 top
C281  2.2uF  [CC0402_HD]  104.39 127.76 90 top
C282  2.2uF  [CC0402_HD]  105.41 127.76 90 top
C283  3300pF  [CC0402_HD]  106.68 127.76 90 top
C284  3300pF  [CC0402_HD]  108.71 127.76 90 top
C285  2.2uF  [CC0402_HD]  109.98 127.76 90 top
C286  2.2uF  [CC0402_HD]  111.25 127.76 90 top
C288  22uF  [1206_CC]  101.73 124.08 270 top
C295  0.1uF  [CC0402_HD]  87 187.58 180 top
C296  0.1uF  [CC0402_HD]  52.45 118.49 90 top
C297  0.1uF  [CC0402_HD]  167.89 118 0 top
C299  0.1uF  [CC0402_HD]  15.37 114.3 0 top
C300  0.1uF  [CC0402_HD]  42.29 112.9 270 top
C303  0.1uF  [CC0402_HD]  167.64 111.89 270 top
C304  0.1uF  [CC0402_HD]  156.97 113.54 90 top
C305  47uF  [CC0805_OV]  36.96 182.32 270 top
C309  0.1uF  [CC0402_HD]  110.96 107.01 180 bottom
C310  0.1uF  [CC0402_HD]  110.97 104.5 180 bottom
C332  0.1uF  [CC0402_HD]  111 103.02 180 bottom
C334  10uF  [CC0603_OV]  112.88 110.53 90 top
C341  10uF  [CC0603_OV]  96.72 88.09 180 bottom
C345  0.1uF  [CC0402_HD]  77.45 72.16 270 top
C346  0.1uF  [CC0402_HD]  84.45 72.16 270 top
C347  0.1uF  [CC0402_HD]  102.13 83.39 90 bottom
C402  0.01UF  [CC0402_HD]  17.14 51.44 0 top
C406  0.01UF  [CC0402_HD]  17.14 50.42 0 top
C412  0.1uF  [CC0402_HD]  215.26 222.88 180 top
C422  0.01UF  [CC0402_HD]  17.14 47.62 0 top
C425  0.01UF  [CC0402_HD]  17.14 46.61 0 top
C433  0.1uF  [CC0402_HD]  96.95 83.03 180 bottom
C434  0.1uF  [CC0402_HD]  227.33 222.63 0 top
C443  0.1uF  [CC0402_HD]  122.68 60.33 270 top
C444  0.1uF  [CC0402_HD]  121.67 60.33 270 top
C445  0.1uF  [CC0402_HD]  124.33 60.33 270 top
C446  0.1uF  [CC0402_HD]  125.35 60.33 270 top
C447  0.1uF  [CC0402_HD]  131.19 60.45 270 top
C448  0.1uF  [CC0402_HD]  132.21 60.45 270 top
C449  0.1uF  [CC0402_HD]  133.6 60.45 270 top
C450  0.1uF  [CC0402_HD]  134.62 60.45 270 top
C451  0.1uF  [CC0402_HD]  164.85 60.33 270 top
C452  0.1uF  [CC0402_HD]  163.83 60.33 270 top
C453  0.1uF  [CC0402_HD]  166.5 60.33 270 top
C454  0.1uF  [CC0402_HD]  167.51 60.33 270 top
C455  0.1uF  [CC0402_HD]  173.35 60.45 270 top
C456  0.1uF  [CC0402_HD]  174.37 60.45 270 top
C457  0.1uF  [CC0402_HD]  175.77 60.45 270 top
C458  0.1uF  [CC0402_HD]  176.78 60.45 270 top
C467  1uF  [CC0603_OV]  191.13 50.9 90 top
C472  10uF  [CC0603_OV]  113.16 58.17 90 top
C481  0.1uF  [CC0402_HD]  215.26 216.65 0 top
C482  0.1uF  [CC0402_HD]  215.26 215.64 0 top
C485  8.2pF  [CC0402_25]  89.02 35.66 90 top
C505  0.1uF  [CC0402_HD]  43.5 50.22 90 top
C515  1uF  [CC0402_HD]  42.88 43.69 180 top
C516  1uF  [CC0402_HD]  32.85 43.69 180 top
C518  0.1uF  [CC0402_HD]  29.82 10.87 270 top
C519  0.1uF  [CC0402_HD]  34.19 18.01 180 top
C520  0.1uF  [CC0402_HD]  26.04 15.75 0 top
C522  0.1uF  [CC0402_HD]  9.88 10.92 0 top
C523  0.1uF  [CC0402_HD]  26.04 11.94 0 top
C546  47uF  [CC0805_OV]  109.58 202.49 0 bottom
C547  47uF  [CC0805_OV]  123.19 202.11 0 bottom
C548  47uF  [CC0805_OV]  123.19 204.6 0 bottom
C549  47uF  [CC0805_OV]  102.54 201.98 0 bottom
C550  47uF  [CC0805_OV]  123.19 199.57 0 bottom
C551  47uF  [CC0805_OV]  109.58 199.69 0 bottom
C552  47uF  [CC0805_OV]  102.54 199.44 0 bottom
C553  47uF  [CC0805_OV]  116.9 199.69 0 bottom
C554  47uF  [CC0805_OV]  123.19 197.28 0 bottom
C555  47uF  [CC0805_OV]  109.58 196.9 0 bottom
C556  47uF  [CC0805_OV]  102.54 197.03 0 bottom
C557  47uF  [CC0805_OV]  116.9 196.9 0 bottom
C562  3300pF  [CC0402_HD]  96.77 194.94 90 bottom
C563  2.2uF  [CC0402_HD]  95.38 194.94 90 bottom
C564  3300pF  [CC0402_HD]  92.58 194.94 90 bottom
C565  2.2uF  [CC0402_HD]  91.31 194.94 90 bottom
C566  10uF  [CC0603_OV]  107.7 191.62 90 bottom
C567  10uF  [CC0603_OV]  105.54 191.62 90 bottom
C568  10uF  [CC0603_OV]  102.13 191.01 180 bottom
C569  10uF  [CC0603_OV]  102.13 188.85 180 bottom
C570  47uF  [CC0805_OV]  126.11 186.69 0 bottom
C571  10uF  [CC0603_OV]  102.36 186.69 0 bottom
C572  10uF  [CC0603_OV]  98.55 186.69 180 bottom
C573  47uF  [CC0805_OV]  70.35 184.78 180 bottom
C574  0.1uF  [CC0402_HD]  112.78 184.15 270 bottom
C575  0.1uF  [CC0402_HD]  110.87 184.15 270 bottom
C576  0.1uF  [CC0402_HD]  109.86 184.15 270 bottom
C577  0.1uF  [CC0402_HD]  119.38 183.64 180 bottom
C578  0.1uF  [CC0402_HD]  114.36 183.64 0 bottom
C579  0.1uF  [CC0402_HD]  108.33 183.64 0 bottom
C580  0.1uF  [CC0402_HD]  87.81 183.18 270 bottom
C581  0.1uF  [CC0402_HD]  84.84 183.18 270 bottom
C582  0.1uF  [CC0402_HD]  82.3 183.64 0 bottom
C583  0.1uF  [CC0402_HD]  80.26 183.64 0 bottom
C584  0.1uF  [CC0402_HD]  78.33 183.64 180 bottom
C585  0.1uF  [CC0402_HD]  80.26 181.74 0 bottom
C586  0.1uF  [CC0402_HD]  54.86 181.36 180 bottom
C587  0.1uF  [CC0402_HD]  119.38 180.72 180 bottom
C588  47uF  [CC0805_OV]  55.5 179.2 0 bottom
C590  0.1uF  [CC0402_HD]  80.26 178.69 0 bottom
C591  0.1uF  [CC0402_HD]  119.38 177.67 180 bottom
C592  47uF  [CC0805_OV]  55.51 177.04 0 bottom
C593  0.1uF  [CC0402_HD]  101.3 176.72 0 bottom
C594  0.1uF  [CC0402_HD]  80.26 176.66 0 bottom
C595  0.1uF  [CC0402_HD]  99.82 176.21 90 bottom
C596  0.1uF  [CC0402_HD]  98.81 176.21 90 bottom
C597  0.1uF  [CC0402_HD]  97.85 176.21 90 bottom
C598  0.1uF  [CC0402_HD]  96.84 176.21 90 bottom
C599  0.1uF  [CC0402_HD]  95.82 176.21 90 bottom
C600  0.1uF  [CC0402_HD]  94.81 176.21 90 bottom
C601  0.1uF  [CC0402_HD]  93.85 176.21 90 bottom
C602  0.1uF  [CC0402_HD]  92.84 176.21 90 bottom
C603  0.1uF  [CC0402_HD]  91.82 176.21 90 bottom
C604  2.2uF  [CC0402_HD]  90.87 176.21 90 bottom
C605  0.1uF  [CC0402_HD]  89.79 176.21 90 bottom
C606  0.1uF  [CC0402_HD]  102.3 175.77 0 bottom
C607  1uF  [CC0402_HD]  109.79 175.2 270 bottom
C608  1uF  [CC0402_HD]  108.84 175.2 270 bottom
C609  1uF  [CC0402_HD]  107.82 175.2 270 bottom
C610  1uF  [CC0402_HD]  106.81 175.2 270 bottom
C611  1uF  [CC0402_HD]  105.79 175.2 270 bottom
C612  0.1uF  [CC0402_HD]  104.9 175.2 270 bottom
C613  0.1uF  [CC0402_HD]  103.82 175.2 270 bottom
C614  2.2uF  [CC0402_HD]  72.39 174.88 180 bottom
C615  0.1uF  [CC0402_HD]  54.48 174.88 180 bottom
C616  3300pF  [CC0402_HD]  99.31 174.75 0 bottom
C617  3300pF  [CC0402_HD]  102.36 174.69 180 bottom
C618  3300pF  [CC0402_HD]  94.36 174.69 180 bottom
C619  3300pF  [CC0402_HD]  92.33 174.69 0 bottom
C620  2.2uF  [CC0402_HD]  100.84 174.31 270 bottom
C621  0.1uF  [CC0402_HD]  89.85 174.18 90 bottom
C622  0.1uF  [CC0402_HD]  119.38 173.74 180 bottom
C623  0.1uF  [CC0402_HD]  80.26 173.67 0 bottom
C624  2.2uF  [CC0402_HD]  72.39 173.61 180 bottom
C625  0.1uF  [CC0402_HD]  93.85 173.16 90 bottom
C626  0.1uF  [CC0402_HD]  103.38 172.72 180 bottom
C627  3300pF  [CC0402_HD]  72.39 172.72 180 bottom
C628  47uF  [CC0805_OV]  60.33 171.96 0 bottom
C629  0.1uF  [CC0402_HD]  109.35 171.7 0 bottom
C630  1uF  [CC0402_HD]  107.31 171.7 180 bottom
C631  1uF  [CC0402_HD]  103.38 171.7 180 bottom
C632  0.1uF  [CC0402_HD]  99.31 171.7 0 bottom
C633  0.1uF  [CC0402_HD]  96.33 171.7 0 bottom
C634  0.1uF  [CC0402_HD]  80.26 171.7 0 bottom
C635  0.1uF  [CC0402_HD]  54.48 171.7 0 bottom
C636  0.1uF  [CC0402_HD]  97.85 171.2 270 bottom
C637  0.1uF  [CC0402_HD]  119.38 170.69 180 bottom
C638  1uF  [CC0402_HD]  111.25 170.69 0 bottom
C639  0.1uF  [CC0402_HD]  109.35 170.69 0 bottom
C640  1uF  [CC0402_HD]  107.31 170.69 0 bottom
C641  1uF  [CC0402_HD]  105.41 170.69 180 bottom
C642  1uF  [CC0402_HD]  103.38 170.69 0 bottom
C643  0.1uF  [CC0402_HD]  101.35 170.69 0 bottom
C644  0.1uF  [CC0402_HD]  99.31 170.69 0 bottom
C645  0.1uF  [CC0402_HD]  96.33 170.69 0 bottom
C646  0.1uF  [CC0402_HD]  109.35 169.67 0 bottom
C647  1uF  [CC0402_HD]  107.31 169.67 180 bottom
C648  1uF  [CC0402_HD]  105.41 169.67 180 bottom
C649  1uF  [CC0402_HD]  103.38 169.67 180 bottom
C650  0.1uF  [CC0402_HD]  99.31 169.67 0 bottom
C651  0.1uF  [CC0402_HD]  97.41 169.67 180 bottom
C652  0.1uF  [CC0402_HD]  95.38 169.67 0 bottom
C653  0.1uF  [CC0402_HD]  80.26 169.67 0 bottom
C654  0.1uF  [CC0402_HD]  93.85 169.16 270 bottom
C655  0.1uF  [CC0402_HD]  92.84 169.16 270 bottom
C656  0.1uF  [CC0402_HD]  111.25 168.66 0 bottom
C657  0.1uF  [CC0402_HD]  109.35 168.66 0 bottom
C658  1uF  [CC0402_HD]  107.31 161.73 180 bottom
C659  1uF  [CC0402_HD]  93.34 159.7 0 bottom
C660  1uF  [CC0402_HD]  103.38 168.66 0 bottom
C661  1uF  [CC0402_HD]  93.34 160.72 0 bottom
C662  1uF  [CC0402_HD]  99.31 168.66 0 bottom
C663  1uF  [CC0402_HD]  97.41 168.66 0 bottom
C664  1uF  [CC0402_HD]  95.38 168.66 0 bottom
C665  0.1uF  [CC0402_HD]  91.31 168.66 180 bottom
C666  0.1uF  [CC0402_HD]  41.48 168.4 90 bottom
C667  0.1uF  [CC0402_HD]  54.48 168.02 0 bottom
C668  0.1uF  [CC0402_HD]  109.35 167.7 0 bottom
C669  1uF  [CC0402_HD]  107.31 167.7 180 bottom
C670  1uF  [CC0402_HD]  105.41 167.7 180 bottom
C671  1uF  [CC0402_HD]  103.38 167.7 0 bottom
C672  1uF  [CC0402_HD]  107.31 159.7 180 bottom
C673  1uF  [CC0402_HD]  99.31 167.7 0 bottom
C674  1uF  [CC0402_HD]  97.41 167.7 180 bottom
C675  1uF  [CC0402_HD]  95.38 167.7 0 bottom
C676  1uF  [CC0402_HD]  93.34 167.7 0 bottom
C677  0.1uF  [CC0402_HD]  91.31 167.7 180 bottom
C678  0.1uF  [CC0402_HD]  80.26 167.7 180 bottom
C679  0.1uF  [CC0402_HD]  111.25 167.64 0 bottom
C680  0.1uF  [CC0402_HD]  109.35 166.75 0 bottom
C681  1uF  [CC0402_HD]  107.31 166.75 0 bottom
C682  1uF  [CC0402_HD]  105.41 166.75 0 bottom
C683  1uF  [CC0402_HD]  105.41 160.72 180 bottom
C684  1uF  [CC0402_HD]  107.31 158.69 0 bottom
C685  1uF  [CC0402_HD]  99.31 166.75 0 bottom
C686  1uF  [CC0402_HD]  103.38 160.72 180 bottom
C687  1uF  [CC0402_HD]  95.38 166.75 180 bottom
C688  1uF  [CC0402_HD]  93.34 166.75 180 bottom
C689  0.1uF  [CC0402_HD]  91.31 166.75 180 bottom
C690  0.1uF  [CC0402_HD]  120.4 166.62 180 bottom
C691  2.2uF  [CC0402_HD]  72.39 165.86 180 bottom
C692  0.1uF  [CC0402_HD]  120.4 165.74 180 bottom
C693  0.1uF  [CC0402_HD]  109.35 165.74 0 bottom
C694  1uF  [CC0402_HD]  107.31 165.74 180 bottom
C695  1uF  [CC0402_HD]  107.31 160.72 0 bottom
C696  1uF  [CC0402_HD]  105.41 158.69 180 bottom
C697  1uF  [CC0402_HD]  101.35 162.69 180 bottom
C698  1uF  [CC0402_HD]  105.41 157.67 180 bottom
C699  1uF  [CC0402_HD]  99.31 162.69 180 bottom
C700  1uF  [CC0402_HD]  93.34 162.69 0 bottom
C701  1uF  [CC0402_HD]  93.34 157.67 180 bottom
C702  0.1uF  [CC0402_HD]  91.31 165.74 180 bottom
C703  0.1uF  [CC0402_HD]  89.79 165.23 90 bottom
C704  0.1uF  [CC0402_HD]  88.77 165.23 90 bottom
C705  0.1uF  [CC0402_HD]  79.76 165.1 0 bottom
C706  1uF  [CC0402_HD]  99.31 164.72 0 bottom
C707  1uF  [CC0402_HD]  93.34 161.73 180 bottom
C708  0.1uF  [CC0402_HD]  91.31 164.72 180 bottom
C709  3300pF  [CC0402_HD]  72.39 164.59 180 bottom
C710  47uF  [CC0805_OV]  126.24 163.83 0 bottom
C711  1uF  [CC0402_HD]  105.41 168.66 0 bottom
C712  1uF  [CC0402_HD]  101.35 168.66 180 bottom
C713  1uF  [CC0402_HD]  103.38 164.72 180 bottom
C714  0.1uF  [CC0402_HD]  92.33 163.7 180 bottom
C715  1uF  [CC0402_HD]  90.3 163.7 0 bottom
C716  2.2uF  [CC0402_HD]  72.39 163.7 180 bottom
C717  47uF  [CC0805_OV]  55.61 163.45 180 bottom
C718  0.1uF  [CC0402_HD]  109.35 162.69 0 bottom
C719  0.1uF  [CC0402_HD]  107.31 162.69 180 bottom
C720  1uF  [CC0402_HD]  105.41 162.69 180 bottom
C721  1uF  [CC0402_HD]  103.38 162.69 0 bottom
C722  1uF  [CC0402_HD]  101.35 165.74 0 bottom
C723  1uF  [CC0402_HD]  97.41 165.74 0 bottom
C724  1uF  [CC0402_HD]  97.28 162.69 0 bottom
C725  1uF  [CC0402_HD]  95.38 162.69 0 bottom
C726  1uF  [CC0402_HD]  95.38 165.74 180 bottom
C727  0.1uF  [CC0402_HD]  91.31 162.69 180 bottom
C728  10uF  [CC0603_OV]  76.45 162.56 90 bottom
C729  1uF  [CC0402_HD]  107.31 168.66 0 bottom
C730  1uF  [CC0402_HD]  105.41 161.73 180 bottom
C731  1uF  [CC0402_HD]  103.38 161.73 180 bottom
C732  1uF  [CC0402_HD]  101.35 161.73 180 bottom
C733  1uF  [CC0402_HD]  99.31 161.73 0 bottom
C734  1uF  [CC0402_HD]  97.28 161.73 0 bottom
C735  1uF  [CC0402_HD]  95.38 161.73 180 bottom
C736  1uF  [CC0402_HD]  95.38 164.72 0 bottom
C737  0.1uF  [CC0402_HD]  91.31 161.73 180 bottom
C741  0.1uF  [CC0402_HD]  109.35 161.67 0 bottom
C742  0.1uF  [CC0402_HD]  80.39 161.67 0 bottom
C743  0.1uF  [CC0402_HD]  109.35 160.72 0 bottom
C744  1uF  [CC0402_HD]  105.41 165.74 180 bottom
C745  1uF  [CC0402_HD]  103.38 165.74 0 bottom
C746  1uF  [CC0402_HD]  97.41 166.75 180 bottom
C747  1uF  [CC0402_HD]  101.35 160.72 180 bottom
C748  1uF  [CC0402_HD]  99.31 160.72 180 bottom
C749  1uF  [CC0402_HD]  97.28 160.72 180 bottom
C750  1uF  [CC0402_HD]  95.38 160.72 180 bottom
C751  1uF  [CC0402_HD]  105.41 164.72 180 bottom
C752  0.1uF  [CC0402_HD]  91.31 160.72 180 bottom
C753  0.1uF  [CC0402_HD]  80.39 160.66 0 bottom
C754  0.1uF  [CC0402_HD]  54.48 160.02 180 bottom
C755  0.1uF  [CC0402_HD]  109.35 159.7 0 bottom
C756  1uF  [CC0402_HD]  101.35 167.7 0 bottom
C757  1uF  [CC0402_HD]  105.41 159.7 180 bottom
C758  1uF  [CC0402_HD]  103.38 159.7 180 bottom
C759  1uF  [CC0402_HD]  101.35 159.7 180 bottom
C760  1uF  [CC0402_HD]  99.31 159.7 180 bottom
C761  1uF  [CC0402_HD]  97.28 159.7 180 bottom
C762  1uF  [CC0402_HD]  95.38 159.7 0 bottom
C763  1uF  [CC0402_HD]  107.31 164.72 180 bottom
C764  0.1uF  [CC0402_HD]  91.31 159.7 180 bottom
C765  0.1uF  [CC0402_HD]  79.38 159.64 0 bottom
C766  0.1uF  [CC0402_HD]  120.27 159.51 270 bottom
C770  0.1uF  [CC0402_HD]  54.48 159 180 bottom
C771  1uF  [CC0402_HD]  101.35 166.75 180 bottom
C772  1uF  [CC0402_HD]  103.38 166.75 0 bottom
C773  1uF  [CC0402_HD]  103.38 158.69 180 bottom
C774  1uF  [CC0402_HD]  101.35 158.69 0 bottom
C775  1uF  [CC0402_HD]  99.31 158.69 0 bottom
C776  1uF  [CC0402_HD]  97.28 158.69 0 bottom
C777  1uF  [CC0402_HD]  95.38 158.69 180 bottom
C778  1uF  [CC0402_HD]  97.28 164.72 0 bottom
C779  0.1uF  [CC0402_HD]  91.31 158.69 180 bottom
C780  0.1uF  [CC0402_HD]  111.76 158.24 90 bottom
C781  0.1uF  [CC0402_HD]  110.74 158.24 90 bottom
C782  10uF  [CC0603_OV]  76.58 158.24 90 bottom
C786  0.1uF  [CC0402_HD]  109.35 157.73 0 bottom
C787  0.1uF  [CC0402_HD]  107.31 157.73 180 bottom
C788  0.1uF  [CC0402_HD]  90.3 157.73 0 bottom
C789  1uF  [CC0402_HD]  99.31 165.74 180 bottom
C790  1uF  [CC0402_HD]  103.38 157.67 180 bottom
C791  1uF  [CC0402_HD]  101.35 157.67 180 bottom
C792  1uF  [CC0402_HD]  99.31 157.67 180 bottom
C793  1uF  [CC0402_HD]  97.28 157.67 180 bottom
C794  1uF  [CC0402_HD]  95.38 157.67 180 bottom
C795  1uF  [CC0402_HD]  93.34 165.74 180 bottom
C796  0.1uF  [CC0402_HD]  91.82 157.23 270 bottom
C800  1uF  [CC0402_HD]  110.36 156.72 180 bottom
C801  0.1uF  [CC0402_HD]  97.28 156.72 0 bottom
C802  1uF  [CC0402_HD]  95.38 156.72 0 bottom
C803  0.1uF  [CC0402_HD]  108.84 156.21 270 bottom
C804  1uF  [CC0402_HD]  101.35 169.67 0 bottom
C805  0.1uF  [CC0402_HD]  106.93 156.21 90 bottom
C806  0.1uF  [CC0402_HD]  105.92 156.21 90 bottom
C807  0.1uF  [CC0402_HD]  104.9 156.21 270 bottom
C808  0.1uF  [CC0402_HD]  103.89 156.21 90 bottom
C809  0.1uF  [CC0402_HD]  102.87 156.21 270 bottom
C810  0.1uF  [CC0402_HD]  101.85 156.21 270 bottom
C811  0.1uF  [CC0402_HD]  100.84 156.21 270 bottom
C812  0.1uF  [CC0402_HD]  99.82 156.21 270 bottom
C813  0.1uF  [CC0402_HD]  98.81 156.21 270 bottom
C817  0.1uF  [CC0402_HD]  120.4 155.7 180 bottom
C818  0.1uF  [CC0402_HD]  96.27 155.7 0 bottom
C819  0.1uF  [CC0402_HD]  92.33 155.7 180 bottom
C821  47uF  [CC0805_OV]  86.36 155.07 180 bottom
C822  47uF  [CC0805_OV]  55.63 155.07 0 bottom
C823  0.1uF  [CC0402_HD]  120.4 154.69 180 bottom
C824  0.1uF  [CC0402_HD]  96.27 154.69 180 bottom
C825  0.1uF  [CC0402_HD]  93.34 154.69 0 bottom
C827  0.1uF  [CC0402_HD]  108.84 154.18 270 bottom
C828  0.1uF  [CC0402_HD]  107.82 154.18 270 bottom
C829  0.1uF  [CC0402_HD]  106.81 154.18 90 bottom
C830  0.1uF  [CC0402_HD]  101.85 154.18 270 bottom
C831  0.1uF  [CC0402_HD]  94.74 154.18 270 bottom
C832  0.1uF  [CC0402_HD]  91.82 154.18 270 bottom
C833  3300pF  [CC0402_HD]  90.81 154.18 90 bottom
C834  0.1uF  [CC0402_HD]  89.79 154.18 90 bottom
C835  0.1uF  [CC0402_HD]  100.71 153.8 270 bottom
C836  0.1uF  [CC0402_HD]  120.4 153.67 180 bottom
C837  3300pF  [CC0402_HD]  93.85 153.16 270 bottom
C838  0.1uF  [CC0402_HD]  92.84 153.16 270 bottom
C839  47uF  [CC0805_OV]  55.63 152.78 0 bottom
C840  0.1uF  [CC0402_HD]  90.3 152.65 0 bottom
C841  3300pF  [CC0402_HD]  105.28 151.64 180 bottom
C842  3300pF  [CC0402_HD]  102.36 151.64 0 bottom
C843  3300pF  [CC0402_HD]  94.36 151.64 0 bottom
C844  0.1uF  [CC0402_HD]  91.82 151.13 270 bottom
C845  3300pF  [CC0402_HD]  98.3 150.75 180 bottom
C846  0.1uF  [CC0402_HD]  96.32 150.7 180 bottom
C847  3300pF  [CC0402_HD]  90.3 150.75 0 bottom
C848  0.1uF  [CC0402_HD]  109.35 150.62 0 bottom
C849  0.1uF  [CC0402_HD]  107.82 150.11 90 bottom
C850  0.1uF  [CC0402_HD]  106.81 150.11 270 bottom
C851  0.1uF  [CC0402_HD]  105.79 150.11 270 bottom
C852  0.1uF  [CC0402_HD]  104.78 150.11 270 bottom
C853  0.1uF  [CC0402_HD]  103.84 150.18 90 bottom
C854  0.1uF  [CC0402_HD]  102.87 150.11 270 bottom
C855  0.1uF  [CC0402_HD]  101.83 150.19 270 bottom
C856  0.1uF  [CC0402_HD]  100.84 150.11 270 bottom
C857  0.1uF  [CC0402_HD]  120.4 149.73 180 bottom
C858  0.1uF  [CC0402_HD]  97.28 149.73 180 bottom
C859  2.2uF  [CC0402_HD]  90.3 149.73 0 bottom
C860  22uF  [1206_CC]  85.92 149.67 180 bottom
C861  0.1uF  [CC0402_HD]  98.81 149.22 270 bottom
C862  0.1uF  [CC0402_HD]  95.76 149.22 270 bottom
C863  0.1uF  [CC0402_HD]  94.87 149.22 270 bottom
C864  0.1uF  [CC0402_HD]  93.85 149.22 270 bottom
C865  0.1uF  [CC0402_HD]  92.84 149.22 270 bottom
C866  0.1uF  [CC0402_HD]  91.82 149.22 270 bottom
C867  2.2uF  [CC0402_HD]  76.2 148.97 270 bottom
C868  22uF  [1206_CC]  74.42 148.59 270 bottom
C869  0.1uF  [CC0402_HD]  120.4 147.7 180 bottom
C870  0.1uF  [CC0402_HD]  120.27 143.76 180 bottom
C871  0.01UF  [CC0402_HD]  87.76 143.26 90 bottom
C872  0.1uF  [CC0402_HD]  120.84 142.11 90 bottom
C873  0.1uF  [CC0402_HD]  119.89 142.11 90 bottom
C874  0.1uF  [CC0402_HD]  116.08 142.11 90 bottom
C875  0.1uF  [CC0402_HD]  114.81 142.11 90 bottom
C876  0.1uF  [CC0402_HD]  113.79 142.11 90 bottom
C877  47uF  [CC0805_OV]  126.11 140.34 0 bottom
C878  10uF  [CC0603_OV]  115.18 139.83 0 bottom
C879  10uF  [CC0603_OV]  82.25 138.43 270 bottom
C880  47uF  [CC0805_OV]  115.18 136.53 0 bottom
C900  0.1uF  [CC0402_HD]  215.39 224.54 180 top
C924  0.1uF  [CC0402_HD]  168.3 54.94 270 bottom
C932  0.1uF  [CC0402_HD]  161.4 51.16 0 bottom
C936  0.1uF  [CC0402_HD]  160.61 56.04 0 bottom
C940  0.1uF  [CC0402_HD]  161.4 53.16 0 bottom
C944  0.1uF  [CC0402_HD]  178.22 54.65 270 bottom
C947  0.1uF  [CC0402_HD]  177.83 52.7 180 bottom
C950  0.1uF  [CC0402_HD]  177.83 50.15 180 bottom
C961  0.1uF  [CC0402_HD]  171.45 54.94 270 bottom
C965  0.1uF  [CC0402_HD]  227.33 223.65 0 top
C987  1uF  [CC0402_HD]  93.34 158.69 180 bottom
C991  0.1uF  [CC0402_HD]  215.26 229.62 180 top
C992  0.1uF  [CC0402_HD]  215.26 231.65 180 top
C993  0.1uF  [CC0402_HD]  215.26 230.63 180 top
C996  0.1uF  [CC0402_HD]  215.26 211.65 0 top
C997  0.1uF  [CC0402_HD]  215.26 210.64 0 top
C998  0.1uF  [CC0402_HD]  215.26 207.65 0 top
C999  0.1uF  [CC0402_HD]  215.26 206.64 0 top
C1000  0.1uF  [CC0402_HD]  215.26 203.65 0 top
C1001  0.1uF  [CC0402_HD]  215.26 202.64 0 top
C1002  0.1uF  [CC0402_HD]  244.35 209.8 0 bottom
C1031  0.22uF  [CC0402_HD]  173.19 96.09 180 top
C1032  0.22uF  [CC0402_HD]  173.19 88.58 180 top
C1033  0.22uF  [CC0402_HD]  173.19 89.5 180 top
C1034  0.22uF  [CC0402_HD]  173.19 97.03 180 top
C1035  0.1uF  [CC0402_HD]  190.02 103.16 0 top
C1036  0.1uF  [CC0402_HD]  190.02 104.07 0 top
C1037  0.1uF  [CC0402_HD]  190.01 110.66 0 top
C1038  0.1uF  [CC0402_HD]  190.01 111.6 0 top
C1109  0.1uF  [CC0402_HD]  185.47 92.43 180 bottom
C1110  0.1uF  [CC0402_HD]  184.12 94.08 270 bottom
C1111  0.1uF  [CC0402_HD]  185.47 90.27 180 bottom
C1112  1uF  [CC0402_HD]  187.22 79.58 270 bottom
C1113  0.1uF  [CC0402_HD]  185.47 89.18 180 bottom
C1141  0.1uF  [CC0402_HD]  201.4 48.16 90 top
C1142  22uF  [CC0603_OV]  206.86 46.99 90 top
C1143  0.1uF  [CC0402_HD]  208.28 46.99 90 top
C1144  0.1uF  [CC0402_HD]  201.4 53.82 90 top
C1145  22uF  [CC0603_OV]  206.86 52.7 90 top
C1146  0.1uF  [CC0402_HD]  208.28 52.7 90 top
C1147  0.1uF  [CC0402_HD]  272.31 53.98 90 top
C1148  22uF  [CC0603_OV]  266.85 52.7 90 top
C1149  0.1uF  [CC0402_HD]  265.43 52.7 90 top
C1150  0.1uF  [CC0402_HD]  272.31 48.26 90 top
C1151  22uF  [CC0603_OV]  266.85 46.99 90 top
C1152  0.1uF  [CC0402_HD]  265.43 46.99 90 top
C1158  1uF  [CC0402_HD]  279.88 84.44 0 top
C1208  0.01UF  [CC0402_HD]  217.17 47.07 270 top
C1209  0.01UF  [CC0402_HD]  218.19 47.07 270 top
C1210  0.01UF  [CC0402_HD]  213.39 47.07 270 top
C1211  0.01UF  [CC0402_HD]  212.37 47.07 270 top
C1212  0.01UF  [CC0402_HD]  232.44 47.07 270 top
C1213  0.01UF  [CC0402_HD]  231.42 47.07 270 top
C1214  0.01UF  [CC0402_HD]  227.63 47.07 270 top
C1215  0.01UF  [CC0402_HD]  226.62 47.07 270 top
C1216  0.01UF  [CC0402_HD]  245.67 47.07 270 top
C1217  0.01UF  [CC0402_HD]  246.68 47.07 270 top
C1218  0.01UF  [CC0402_HD]  241.88 47.07 270 top
C1219  0.01UF  [CC0402_HD]  240.87 47.07 270 top
C1220  0.01UF  [CC0402_HD]  260.93 47.07 270 top
C1221  0.01UF  [CC0402_HD]  259.92 47.07 270 top
C1222  0.01UF  [CC0402_HD]  256.13 47.07 270 top
C1223  0.01UF  [CC0402_HD]  255.12 47.07 270 top
C1224  10pF  [CC0402_HD]  70.48 30.35 0 top
C1225  10pF  [CC0402_HD]  68.33 30.35 0 top
C1226  10pF  [CC0402_HD]  64.01 30.35 0 top
C1227  10pF  [CC0402_HD]  66.17 30.35 0 top
C1229  10pF  [CC0402_HD]  61.85 30.35 0 top
C1230  10pF  [CC0402_HD]  59.69 30.35 0 top
C1231  10pF  [CC0402_HD]  57.53 30.35 0 top
C1232  10pF  [CC0402_HD]  55.37 30.35 0 top
C1240  0.1uF  [CC0402_HD]  182.88 188.85 90 top
C1241  10uF  [CC0603_OV]  168.21 185.17 0 top
C1242  10uF  [CC0603_OV]  168.21 187.07 0 top
C1243  10uF  [CC0603_OV]  168.21 188.85 0 top
C1247  0.1uF  [CC0402_HD]  171.45 181.1 90 top
C1250  0.1uF  [CC0402_HD]  36.96 197.74 180 top
C1251  10uF  [CC0603_OV]  40.64 182.32 270 top
C1252  10uF  [CC0603_OV]  41.21 235.46 180 top
C1253  10uF  [CC0603_OV]  38.89 182.32 270 top
C1254  10uF  [CC0603_OV]  170.18 180.97 270 top
C1256  10uF  [CC0603_OV]  41.21 233.81 180 top
C1257  0.1uF  [CC0402_HD]  41.21 236.73 0 top
C1259  1uF  [CC0603_OV]  131.95 34.77 90 top
C1260  1uF  [CC0603_OV]  173.61 34.77 90 top
C1261  1uF  [CC0603_OV]  49.53 26.04 90 top
C1262  1uF  [CC0603_OV]  72.14 24.13 90 top
C1263  1uF  [CC0603_OV]  75.67 13.31 90 top
C1264  1uF  [CC0603_OV]  109.09 13.34 90 top
C1265  47uF  [CC0805_OV]  109.22 139.32 0 bottom
C1266  1uF  [CC0603_OV]  20.07 244.35 0 top
C2636  0.1uF  [CC0402_HD]  77.64 202.17 0 top
C2637  0.1uF  [CC0402_HD]  89.07 202.17 180 top
C2673  0.1uF  [CC0402_HD]  15.34 216.11 90 top
C2679  0.1uF  [CC0402_HD]  32.25 227.97 270 top
C2680  0.1uF  [CC0402_HD]  24.38 227.33 270 top
C2704  1uF  [CC0402_HD]  67.59 39.8 0 top
C2705  1uF  [CC0402_HD]  58.95 39.85 0 top
C3690  27pF  [CC0402_25]  52.65 81.28 90 top
C3691  27pF  [CC0402_25]  52.65 79.12 270 top
C3697  22uF  [CC0805]  52.91 71.15 90 bottom
C3698  0.1uF  [CC0402_HD]  58.94 71.98 135 bottom
C3699  0.1uF  [CC0402_HD]  1.99 69.39 90 bottom
C3700  0.1uF  [CC0402_HD]  13.32 71.94 90 bottom
C3701  0.1uF  [CC0201]  54.69 80.8 180 bottom
C3702  0.1uF  [CC0201]  55.87 81.15 90 bottom
C3703  0.1uF  [CC0201]  55.47 75.21 180 bottom
C3710  0.1uF  [CC0201]  64.41 75.31 0 bottom
C3711  0.1uF  [CC0201]  56.31 76.81 180 bottom
C3712  0.1uF  [CC0201]  58.72 76 180 bottom
C3713  0.1uF  [CC0201]  58.27 77.17 90 bottom
C3714  0.1uF  [CC0201]  59.05 74.8 90 bottom
C3716  0.1uF  [CC0201]  55.07 73.2 90 bottom
C3717  0.1uF  [CC0201]  57.71 71.75 315 bottom
C3718  0.1uF  [CC0201]  57.99 74.12 225 bottom
C3719  0.1uF  [CC0201]  65.71 72.24 45 bottom
C3720  0.1uF  [CC0201]  67.07 68.4 270 bottom
C3721  0.1uF  [CC0201]  64.41 69.34 225 bottom
C3722  0.1uF  [CC0201]  58.14 73.03 225 bottom
C3723  0.1uF  [CC0201]  63.53 71.98 0 bottom
C3724  0.1uF  [CC0201]  54.84 85.39 90 bottom
C3725  0.1uF  [CC0201]  61.47 74.8 270 bottom
C3728  0.1uF  [CC0201]  61.47 73.2 270 bottom
C3729  0.1uF  [CC0201]  62.27 73.2 90 bottom
C3730  0.1uF  [CC0201]  63.78 73.53 45 bottom
C3731  0.1uF  [CC0201]  66.12 66.5 0 bottom
C3732  0.1uF  [CC0201]  59.87 73.2 270 bottom
C3733  0.1uF  [CC0201]  60.66 73.2 90 bottom
C3734  0.1uF  [CC0201]  59.87 74.8 270 bottom
C3735  0.1uF  [CC0201]  60.67 74.8 90 bottom
C3736  0.1uF  [CC0201]  60.66 76.4 90 bottom
C3737  0.1uF  [CC0201]  62.26 74.8 90 bottom
C3738  0.1uF  [CC0201]  62.26 76.4 90 bottom
C3739  0.1uF  [CC0201]  61.47 76.4 270 bottom
C3742  22uF  [CC0805]  66.12 63.91 0 bottom
C3743  22uF  [CC0805]  52.2 85.5 90 bottom
C3744  1uF  [CC0402_HD]  66.12 65.56 0 bottom
C3745  1uF  [CC0402_HD]  53.82 85.39 90 bottom
C3747  0.1uF  [CC0402_HD]  249.82 158.59 180 bottom
C3831  0.1uF  [CC0402_HD]  53.11 75.69 0 bottom
C3836  0.1uF  [CC0201]  63.07 81.14 90 bottom
C3837  0.1uF  [CC0201]  57.23 80.25 135 bottom
C3838  0.1uF  [CC0201]  62.26 69.37 270 bottom
C3839  0.1uF  [CC0201]  55.6 69.62 180 bottom
C3840  0.1uF  [CC0201]  66.83 77.06 135 bottom
C3841  0.1uF  [CC0201]  63.07 76.4 270 bottom
C3842  0.1uF  [CC0201]  63.07 74.8 270 bottom
C3843  0.1uF  [CC0201]  60.22 68.83 0 bottom
C3844  0.1uF  [CC0402_HD]  241.86 195.33 180 top
C3847  0.1uF  [CC0402_HD]  280 77.84 0 top
C3848  0.1uF  [CC0402_HD]  246.09 216.15 270 top
C3849  0.1uF  [CC0402_HD]  90.02 116.69 0 top
C3850  0.1uF  [CC0402_HD]  83.52 116.69 180 top
C3851  0.1uF  [CC0402_HD]  75.29 116.69 0 top
C3852  0.1uF  [CC0402_HD]  68.78 116.69 180 top
C3853  1uF  [CC0402_HD]  121.23 81.93 90 bottom
C3854  1uF  [CC0402_HD]  124.8 84.48 180 bottom
C3855  1uF  [CC0402_HD]  122.25 81.93 90 bottom
C3856  1uF  [CC0402_HD]  124.8 86 180 bottom
C3857  10uF  [CC0603_OV]  130.68 91.97 0 top
C3858  0.1uF  [CC0402_HD]  129.95 92.49 90 bottom
C3859  10uF  [CC0603_OV]  125.17 80.92 180 bottom
C3860  1uF  [CC0402_HD]  126.31 88.08 90 bottom
C3861  1uF  [CC0402_HD]  120.21 87.53 270 bottom
C3862  1uF  [CC0402_HD]  125.29 79.53 180 bottom
C3863  1uF  [CC0402_HD]  123.27 81.93 90 bottom
C3864  1uF  [CC0402_HD]  124.65 87.37 225 bottom
C3865  1uF  [CC0402_HD]  113.06 81.03 270 bottom
C3866  1uF  [CC0402_HD]  115.9 81.04 270 top
C3867  1uF  [CC0402_HD]  124.8 82.45 180 bottom
C3868  1uF  [CC0402_HD]  123.01 87.53 270 bottom
C3869  1uF  [CC0402_HD]  124.8 83.46 180 bottom
C3870  1uF  [CC0402_HD]  121.75 87.53 270 bottom
C3873  0.1uF  [CC0402_HD]  130.13 83.08 0 top
C3874  0.1uF  [CC0402_HD]  130.13 82.07 0 top
C3881  0.1uF  [CC0402_HD]  123.98 77 270 top
C3882  0.1uF  [CC0402_HD]  123.01 77 270 top
C3889  10uF  [CC0603_OV]  103.84 110.53 90 top
C3890  0.1uF  [CC0402_HD]  108.46 108 270 bottom
C3891  0.1uF  [CC0402_HD]  105.41 105.49 0 bottom
C3892  0.1uF  [CC0402_HD]  106.96 102.49 90 bottom
C3893  0.22uF  [CC0402_HD]  68.58 36.57 270 bottom
C3894  1uF  [CC0402_TOL0P2]  67.52 33.52 0 top
C3895  1uF  [CC0402_TOL0P2]  69.85 36.1 270 top
C3896  0.22uF  [CC0402_HD]  59.94 36.63 270 bottom
C3897  1uF  [CC0402_TOL0P2]  58.88 33.58 0 top
C3898  1uF  [CC0402_TOL0P2]  61.21 36.15 270 top
